// SIMATIC S7-200 SMART project (STEP 7-Micro/WIN SMART), CPU ST60

SYMBOL_TABLE Modbus TCP
//接收的MCD数据
MiddleLS         V1227.0  // 40014.0 传送带中间位置信号
EndLS            V1227.1  // 40014.1 传送带末端位置信号
GripperOpened    V1227.2  // 40014.2  夹具打开信号
GripperClosed    V1227.3  // 40014.3 夹具关闭信号
// 输出到MCD        ?0_40_0
PosAxisX         VD1200   // 40001 轴位置值
PosAxisY         VD1204   // 40003
PosAxisZ         VD1208   // 40005
PosRotat         VD1232   // 40017
SpdAxisX         VD1212   // 40007 轴速度值
SpdAxisY         VD1216   // 40009
SpdAxisZ         VD1220   // 40011
Spd3D            VD1240   // 轴组速度
SpdR             VD3500   // 旋转轴速度
SpdRotat         VD3000   // HMI 输入的旋转轴速度设置
GripperClose     V1225.0  // 40013.0 关闭夹具信号
GripperOpen      V1225.1  // 40013.1 打开夹具信号
ConvStart        V1225.2  // 40013.2 开启传送带信号
// Test Cycle    ?0_40_0
CycleNo          VW1228   // 40015 循环序号
END_SYMBOL_TABLE

SYMBOL_TABLE 系统符号
Always_On        SM0.0    // 始终接通
END_SYMBOL_TABLE

SYMBOL_TABLE movePath
///
///                       // 以下为  部分常量数值
AFTPICK          4
AFTPLACE         8
DISTANCE_PREOPERATION 10.0
ERR_AREA_RESERVED 16#8800
ERR_IN_BLOCK_OPERATION 16#8001
ERR_PARAMETRIZATION 16#8200
ERR_PROCESSING_EXTERN 16#8400
ERR_PROCESSING_INTERN 16#8600
ERR_UNDEFINED_STATE 16#8600
ERR_USER_DEFINED_CLASSE 16#9000
moveCmdActive    V1041.2  // 运动状态位
moveCmdBusy      V1041.1
moveCmdDone      V1041.0
moveCmdErr       VB1042
NO_PROCESSING    0
PICK             2
pickPosX         VD1000   // 取料轴坐标位置
pickPosY         VD1004
pickPosZ         VD1008
PLACE            6
placePosX        VD1012   // 放料轴坐标位置
placePosY        VD1016
placePosZ        VD1020
PREPICK          1
PREPLACE         5
rotatCmdDone     V1041.3  // 旋转运动完成
rotatCmdErr      VB1043   // 旋转运动报错
statBusy         V1040.1  // 运动进行中
statDone         V1040.0  // 运动完成
statError        V1040.2  // 运动报错
statGripperClose V1040.4  // 夹具关闭
statGripperOpen  V1040.3  // 夹具打开
statState        VB1050   // 运动步骤序号
statStatus       VW1052   // 运动状态信息
STATUS_EXECUTION_FINISH 16#0
STATUS_FIRST_CALL 16#7001
STATUS_NO_CALL   16#7000
STATUS_SUBSEQUENT_CALL 16#7002
TOOL_PICK        3
TOOL_PLACE       7
WAIT             9
waitPosX         VD1024   // 等待位轴坐标
waitPosY         VD1028
waitPosZ         VD1032
END_SYMBOL_TABLE

SYMBOL_TABLE HMI
EnableAxes       M1.0     // 使能轴组
HomeAxes         M1.1     // 零点设置
StopGroup        M1.2     // 停止轴组运动
ExePnP           M2.0     // 执行搬运
AbortPnP         M2.1     // 终止搬运
DonePnP          M3.0     // 搬运完成
BusyPnP          M3.1     // 搬运中
ErrPnP           M3.2     // 搬运报错
DoneMTS          M7.0     // Modbus subrutine done
XjogN            M7.1     // X轴负向手动运动
XjogP            M7.2     // X轴正向手动运动
XgoHome          M7.3     // X轴回零
YgoHome          M7.4     // Y轴回零
ZgoHome          M7.5     // Z轴回零
RgoHome          M7.6     // 旋转轴回零
EnableButton     M7.7     // 使能按钮
ErrMTS           MB6      // Modbus subrutine error
StatusPnP        MW4      // 搬运状态
END_SYMBOL_TABLE

SYMBOL_TABLE PnP
///
statPnPDone      V1100.0  // 搬运完成
statPnPBusy      V1100.1  // 正在搬运
statPnPError     V1100.2  // 搬运报错
statMovePathDone V1100.3  // 运动完成
statMovePathBusy V1100.4  // 运动中
statMovePathErr  V1100.5  // 运动报错
statCloseCmd     V1100.6  // 夹具关指令
statOpenCmd      V1100.7  // 夹具开指令
statIsClosed     V1101.0  // 夹具关状态
statIsOpened     V1101.1  // 夹具开状态
statStartPnP     V1101.2  // 搬运开始
statStartConveyor V1101.3  // 开启传送带
statPnPState     VB1108   // 搬运步骤
statPnPStatus    VW1102   // 搬运状态信息
statPnPNum       VW1104   // 搬运序号
statMovePathStatus VW1106   // movepath子程序输出状态信息
AddrPick         VB1110   // 取料坐标
PickPosX_Conf    VD1110
PickPosY_Conf    VD1114
PickPosZ_Conf    VD1118
AddrPlace        VB1130   // 放料坐标
PlacePosX_Conf   VD1130
PlacePosY_Conf   VD1134
PlacePosZ_Conf   VD1138
AddrWait         VB1150   // 等待位坐标
waitPosX_Conf    VD1150
WaitPosY_Conf    VD1154
WaitPosZ_Conf    VD1158
DISTANCE_ROWX    35       // 位置间距常量
DISTANCE_ROWY    35
END_SYMBOL_TABLE

ORGANIZATION_BLOCK MAIN:OB1
TITLE==============================================================================
// LIABILITY
// Siemens AG does not accept liability of any kind for damages arising from the use of this application, except where it is obliged to by law, in cases such as damage to items used for personal purposes, personal injury, willful damage or gross negligence.
// =============================================================================
// WARRANTY
// The program examples given are specific solutions to complex tasks which were worked on by Customer Support. We must also point out that it is not possible in the current state of the technology to exclude all errors in software programs under all conditions of use. The program examples were prepared according to the best of our knowledge. However, we cannot accept any liability beyond the standard guarantee for Class C software in accordance with our General Terms of Sale for Software Products for Automation and Drive Technology". The program examples can be purchased on the Internet as single licenses. They may not be transferred to a third party.
// =============================================================================
// 
BEGIN
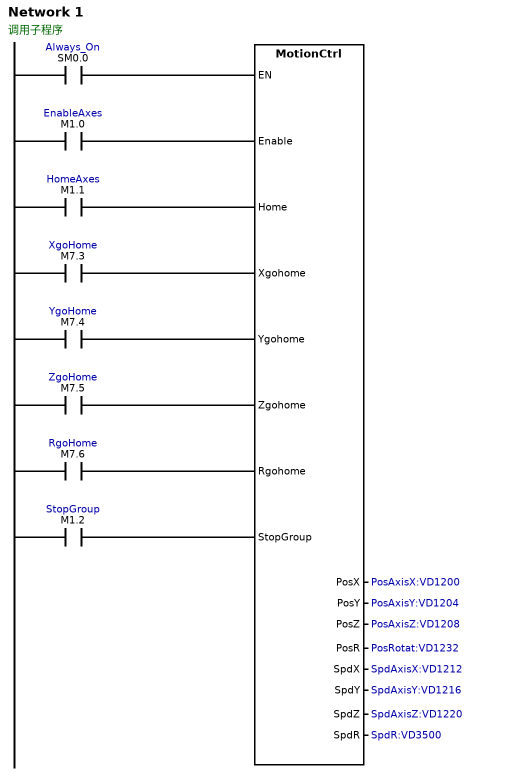
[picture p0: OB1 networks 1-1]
Network 1
// 调用子程序
LD     Always_On:SM0.0
=      L60.0
LD     EnableAxes:M1.0
=      L63.7
LD     HomeAxes:M1.1
=      L63.6
LD     XgoHome:M7.3
=      L63.5
LD     YgoHome:M7.4
=      L63.4
LD     ZgoHome:M7.5
=      L63.3
LD     RgoHome:M7.6
=      L63.2
LD     StopGroup:M1.2
=      L63.1
LD     L60.0
CALL   MotionCtrl:SBR35, L63.7, L63.6, L63.5, L63.4, L63.3, L63.2, L63.1, PosAxisX:VD1200, PosAxisY:VD1204, PosAxisZ:VD1208, PosRotat:VD1232, SpdAxisX:VD1212, SpdAxisY:VD1216, SpdAxisZ:VD1220, SpdR:VD3500
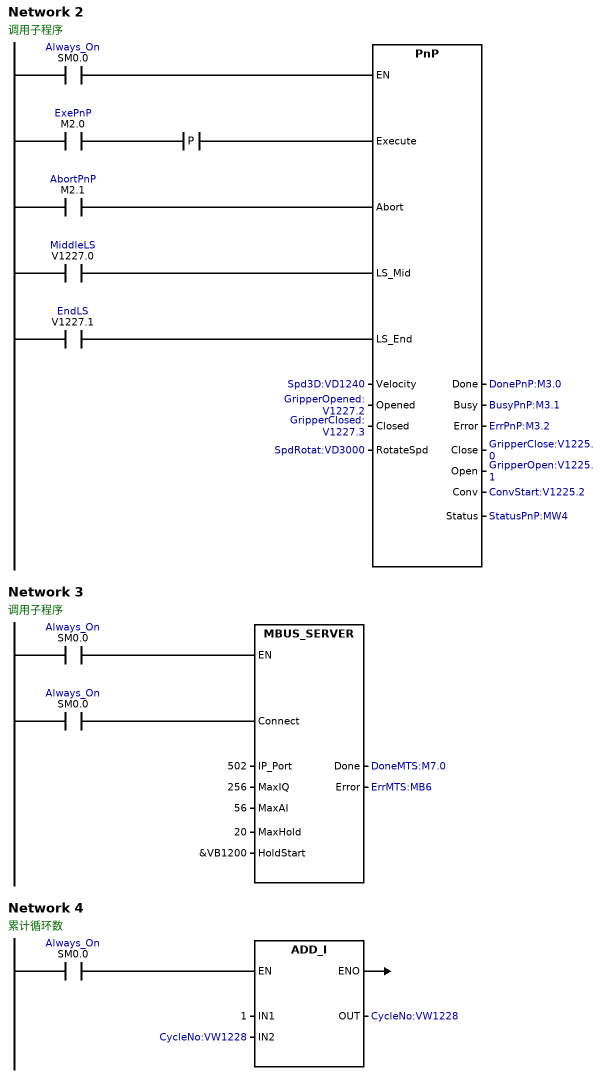
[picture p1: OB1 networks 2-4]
Network 2
// 调用子程序
LD     Always_On:SM0.0
=      L60.0
LD     ExePnP:M2.0
EU
=      L63.7
LD     AbortPnP:M2.1
=      L63.6
LD     MiddleLS:V1227.0
=      L63.5
LD     EndLS:V1227.1
=      L63.4
LD     L60.0
CALL   PnP:SBR36, L63.7, L63.6, L63.5, L63.4, Spd3D:VD1240, GripperOpened:V1227.2, GripperClosed:V1227.3, SpdRotat:VD3000, DonePnP:M3.0, BusyPnP:M3.1, ErrPnP:M3.2, GripperClose:V1225.0, GripperOpen:V1225.1, ConvStart:V1225.2, StatusPnP:MW4
Network 3
// 调用子程序
LD     Always_On:SM0.0
=      L60.0
LD     Always_On:SM0.0
=      L63.7
LD     L60.0
CALL   MBUS_SERVER:SBR39, L63.7, 502, 256, 56, 20, &VB1200, DoneMTS:M7.0, ErrMTS:MB6
Network 4
// 累计循环数
LD     Always_On:SM0.0
+I     1, CycleNo:VW1228
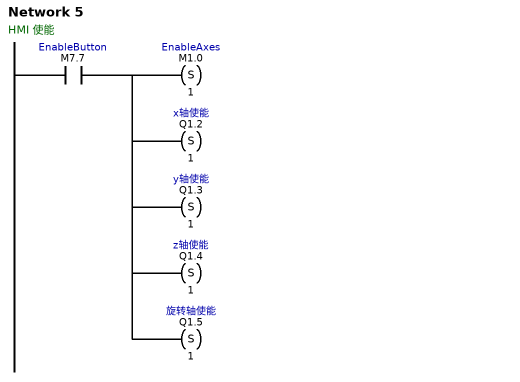
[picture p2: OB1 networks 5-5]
Network 5
// HMI 使能
LD     EnableButton:M7.7
S      EnableAxes:M1.0, 1
S      x轴使能:Q1.2, 1
S      y轴使能:Q1.3, 1
S      z轴使能:Q1.4, 1
S      旋转轴使能:Q1.5, 1
END_ORGANIZATION_BLOCK

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
SUBROUTINE_BLOCK MotionCtrl:SBR35
TITLE=对运动轴和轴组的初始化
VAR_INPUT
Enable:BOOL;	// L0.0 使能输入
Home:BOOL;	// L0.1 设零点
Xgohome:BOOL;	// L0.2 X轴回零点
Ygohome:BOOL;	// L0.3 Y轴回零点
Zgohome:BOOL;	// L0.4 Z轴回零点
Rgohome:BOOL;	// L0.5 旋转轴回零点
StopGroup:BOOL;	// L0.6 停止轴组运动
END_VAR
VAR_OUTPUT
PosX:REAL;	// LD1 X轴位置
PosY:REAL;	// LD5 Y轴位置
PosZ:REAL;	// LD9 Z轴位置
PosR:REAL;	// LD13 旋转轴位置
SpdX:REAL;	// LD17 X轴速度
SpdY:REAL;	// LD21 Y轴速度
SpdZ:REAL;	// LD25 Z轴速度
SpdR:REAL;	// LD29 旋转轴速度
END_VAR
VAR
tempDone0:BOOL;	// L33.0 
tempDone1:BOOL;	// L33.1 
tempDone2:BOOL;	// L33.2 
tempDone3:BOOL;	// L33.3 
tempErr0:BYTE;	// LB34 
tempErr1:BYTE;	// LB35 
tempErr2:BYTE;	// LB36 
tempErr3:BYTE;	// LB37 
tempPos:REAL;	// LD38 
tempSpd:REAL;	// LD42 
tempDir:BOOL;	// L46.0 
tempHome0:BOOL;	// L46.1 
tempHome1:BOOL;	// L46.2 
tempHome2:BOOL;	// L46.3 
tempHome3:BOOL;	// L46.4 
tempStopDone:BOOL;	// L46.5 
tempStopBusy:BOOL;	// L46.6 
tempStopActive:BOOL;	// L46.7 
tempStopErr:BYTE;	// LB47 
tempXhomeDone:BOOL;	// L48.0 
tempXhomeErr:BYTE;	// LB49 
tempYhomeDone:BOOL;	// L50.0 
tempYhomeErr:BYTE;	// LB51 
tempZhomeDone:BOOL;	// L52.0 
tempZhomeErr:BYTE;	// LB53 
tempRhomeErr:BYTE;	// LB54 
tempRun:BOOL;	// L55.0 
dir:BOOL;	// L55.1 
tempRhomeDone:BOOL;	// L55.2 
END_VAR
BEGIN
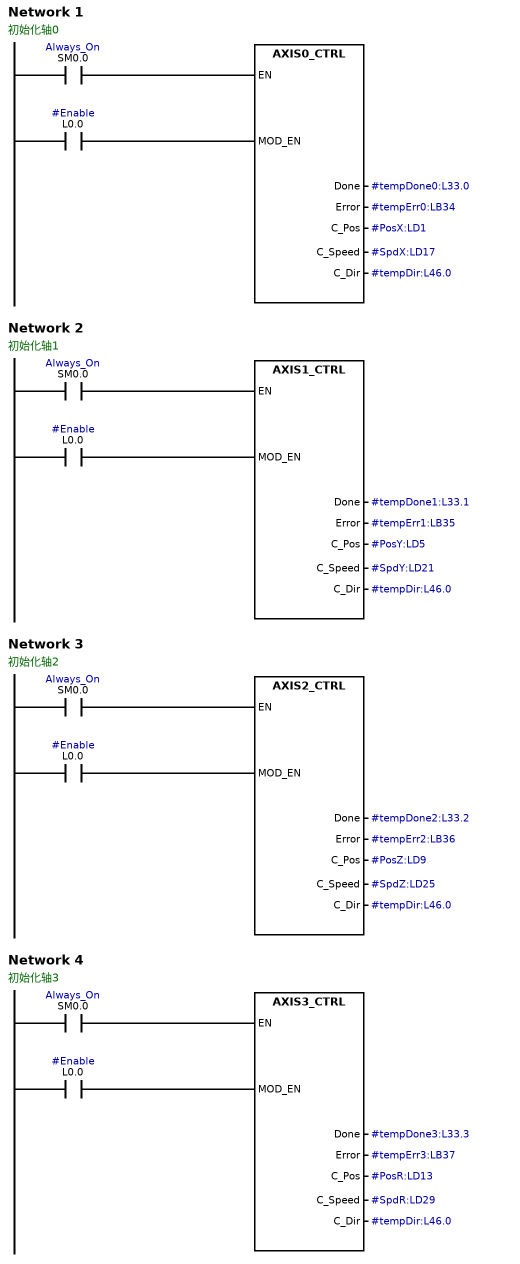
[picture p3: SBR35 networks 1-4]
Network 1
// 初始化轴0
LD     Always_On:SM0.0
=      L60.0
LD     #Enable:L0.0
=      L63.7
LD     L60.0
CALL   AXIS0_CTRL:SBR0, L63.7, #tempDone0:L33.0, #tempErr0:LB34, #PosX:LD1, #SpdX:LD17, #tempDir:L46.0
Network 2
// 初始化轴1
LD     Always_On:SM0.0
=      L60.0
LD     #Enable:L0.0
=      L63.7
LD     L60.0
CALL   AXIS1_CTRL:SBR11, L63.7, #tempDone1:L33.1, #tempErr1:LB35, #PosY:LD5, #SpdY:LD21, #tempDir:L46.0
Network 3
// 初始化轴2
LD     Always_On:SM0.0
=      L60.0
LD     #Enable:L0.0
=      L63.7
LD     L60.0
CALL   AXIS2_CTRL:SBR22, L63.7, #tempDone2:L33.2, #tempErr2:LB36, #PosZ:LD9, #SpdZ:LD25, #tempDir:L46.0
Network 4
// 初始化轴3
LD     Always_On:SM0.0
=      L60.0
LD     #Enable:L0.0
=      L63.7
LD     L60.0
CALL   AXIS3_CTRL:SBR33, L63.7, #tempDone3:L33.3, #tempErr3:LB37, #PosR:LD13, #SpdR:LD29, #tempDir:L46.0
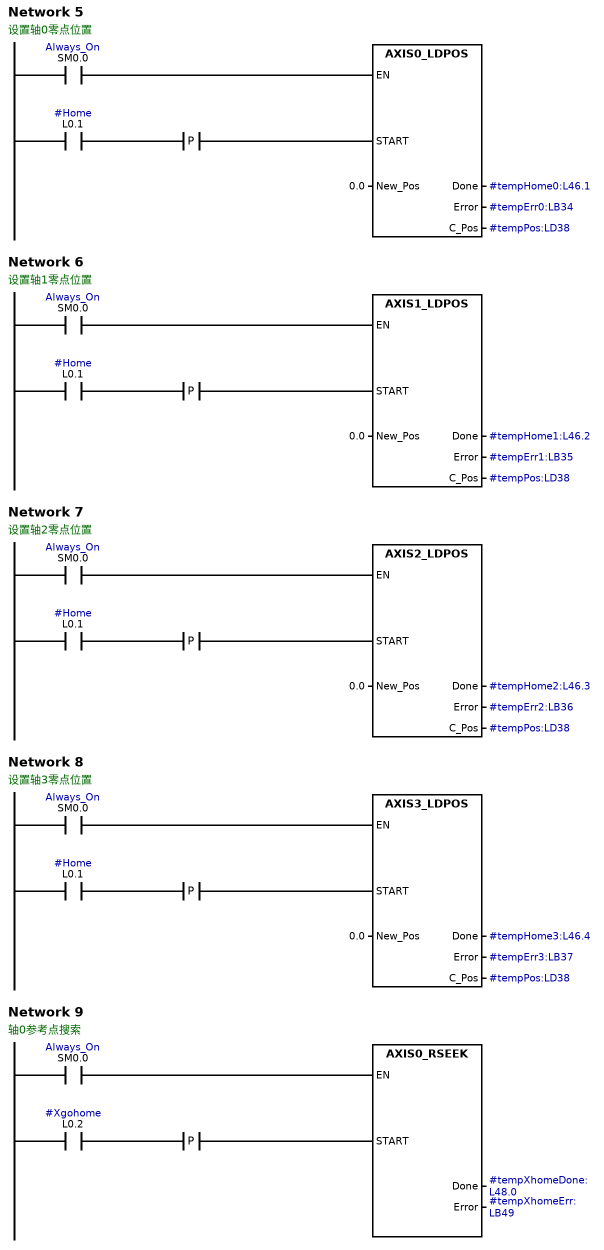
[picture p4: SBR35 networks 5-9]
Network 5
// 设置轴0零点位置
LD     Always_On:SM0.0
=      L60.0
LD     #Home:L0.1
EU
=      L63.7
LD     L60.0
CALL   AXIS0_LDPOS:SBR6, L63.7, 0.0, #tempHome0:L46.1, #tempErr0:LB34, #tempPos:LD38
Network 6
// 设置轴1零点位置
LD     Always_On:SM0.0
=      L60.0
LD     #Home:L0.1
EU
=      L63.7
LD     L60.0
CALL   AXIS1_LDPOS:SBR17, L63.7, 0.0, #tempHome1:L46.2, #tempErr1:LB35, #tempPos:LD38
Network 7
// 设置轴2零点位置
LD     Always_On:SM0.0
=      L60.0
LD     #Home:L0.1
EU
=      L63.7
LD     L60.0
CALL   AXIS2_LDPOS:SBR28, L63.7, 0.0, #tempHome2:L46.3, #tempErr2:LB36, #tempPos:LD38
Network 8
// 设置轴3零点位置
LD     Always_On:SM0.0
=      L60.0
LD     #Home:L0.1
EU
=      L63.7
LD     L60.0
CALL   AXIS3_LDPOS:SBR44, L63.7, 0.0, #tempHome3:L46.4, #tempErr3:LB37, #tempPos:LD38
Network 9
// 轴0参考点搜索
LD     Always_On:SM0.0
=      L60.0
LD     #Xgohome:L0.2
EU
=      L63.7
LD     L60.0
CALL   AXIS0_RSEEK:SBR4, L63.7, #tempXhomeDone:L48.0, #tempXhomeErr:LB49
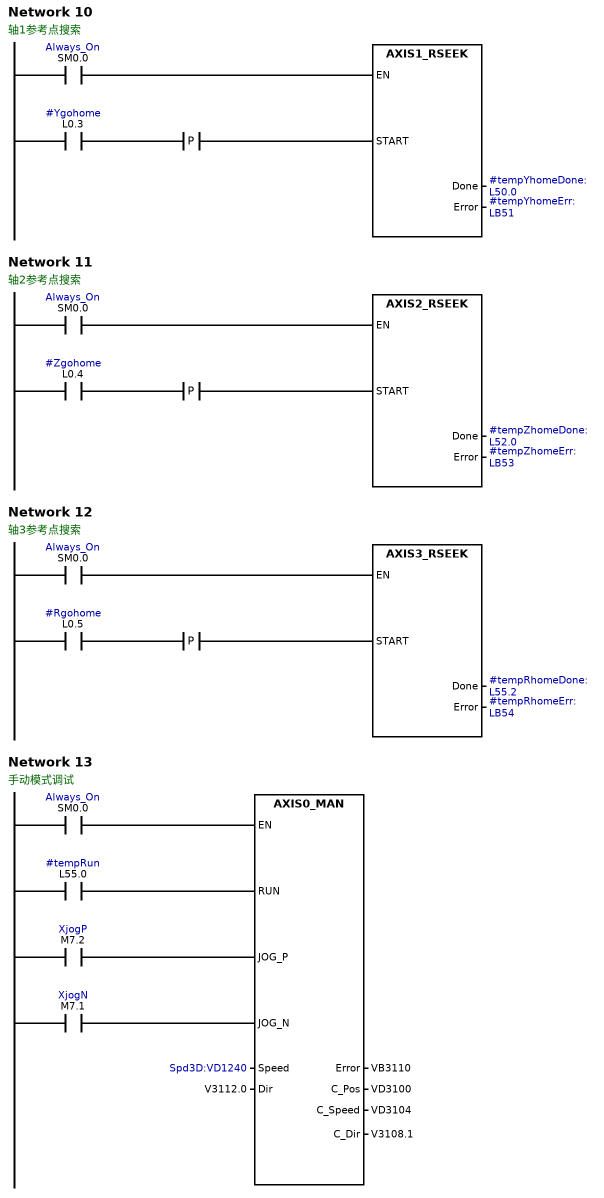
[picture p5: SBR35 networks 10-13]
Network 10
// 轴1参考点搜索
LD     Always_On:SM0.0
=      L60.0
LD     #Ygohome:L0.3
EU
=      L63.7
LD     L60.0
CALL   AXIS1_RSEEK:SBR15, L63.7, #tempYhomeDone:L50.0, #tempYhomeErr:LB51
Network 11
// 轴2参考点搜索
LD     Always_On:SM0.0
=      L60.0
LD     #Zgohome:L0.4
EU
=      L63.7
LD     L60.0
CALL   AXIS2_RSEEK:SBR26, L63.7, #tempZhomeDone:L52.0, #tempZhomeErr:LB53
Network 12
// 轴3参考点搜索
LD     Always_On:SM0.0
=      L60.0
LD     #Rgohome:L0.5
EU
=      L63.7
LD     L60.0
CALL   AXIS3_RSEEK:SBR42, L63.7, #tempRhomeDone:L55.2, #tempRhomeErr:LB54
Network 13
// 手动模式调试
LD     Always_On:SM0.0
=      L60.0
LD     #tempRun:L55.0
=      L63.7
LD     XjogP:M7.2
=      L63.6
LD     XjogN:M7.1
=      L63.5
LD     L60.0
CALL   AXIS0_MAN:SBR1, L63.7, L63.6, L63.5, Spd3D:VD1240, V3112.0, VB3110, VD3100, VD3104, V3108.1
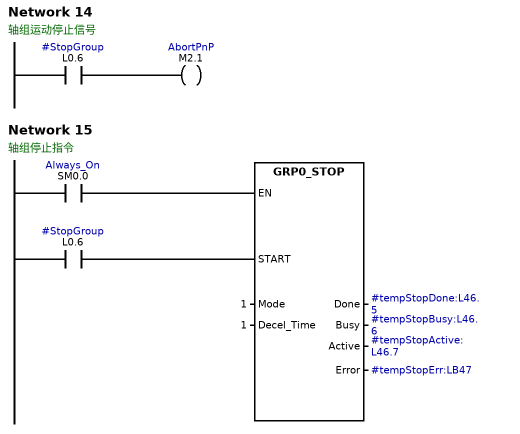
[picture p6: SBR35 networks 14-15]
Network 14
// 轴组运动停止信号
LD     #StopGroup:L0.6
=      AbortPnP:M2.1
Network 15
// 轴组停止指令
LD     Always_On:SM0.0
=      L60.0
LD     #StopGroup:L0.6
=      L63.7
LD     L60.0
CALL   GRP0_STOP:SBR51, L63.7, 1, 1, #tempStopDone:L46.5, #tempStopBusy:L46.6, #tempStopActive:L46.7, #tempStopErr:LB47
END_SUBROUTINE_BLOCK

SUBROUTINE_BLOCK PnP:SBR36
TITLE=搬运流程逻辑
VAR_INPUT
Execute:BOOL;	// L0.0 执行，上升沿触发
Abort:BOOL;	// L0.1 终止搬运
LS_Mid:BOOL;	// L0.2 传送带中间位
LS_End:BOOL;	// L0.3 传送带尾端位
Velocity:REAL;	// LD1 速度值
Opened:BOOL;	// L5.0 打开夹具
Closed:BOOL;	// L5.1 关闭夹具
RotateSpd:REAL;	// LD6 旋转轴速度
END_VAR
VAR_OUTPUT
Done:BOOL;	// L10.0 完成状态位
Busy:BOOL;	// L10.1 忙碌状态位
Error:BOOL;	// L10.2 错误位
Close:BOOL;	// L10.3 夹具关闭
Open:BOOL;	// L10.4 夹具打开
Conv:BOOL;	// L10.5 传送带指令
Status:WORD;	// LW11 状态信息输出
END_VAR
VAR
tempRowX:INT;	// LW13 
tempRowY:INT;	// LW15 
tempPosAddInt:INT;	// LW17 
tempPosAddDint:DINT;	// LD19 
END_VAR
BEGIN
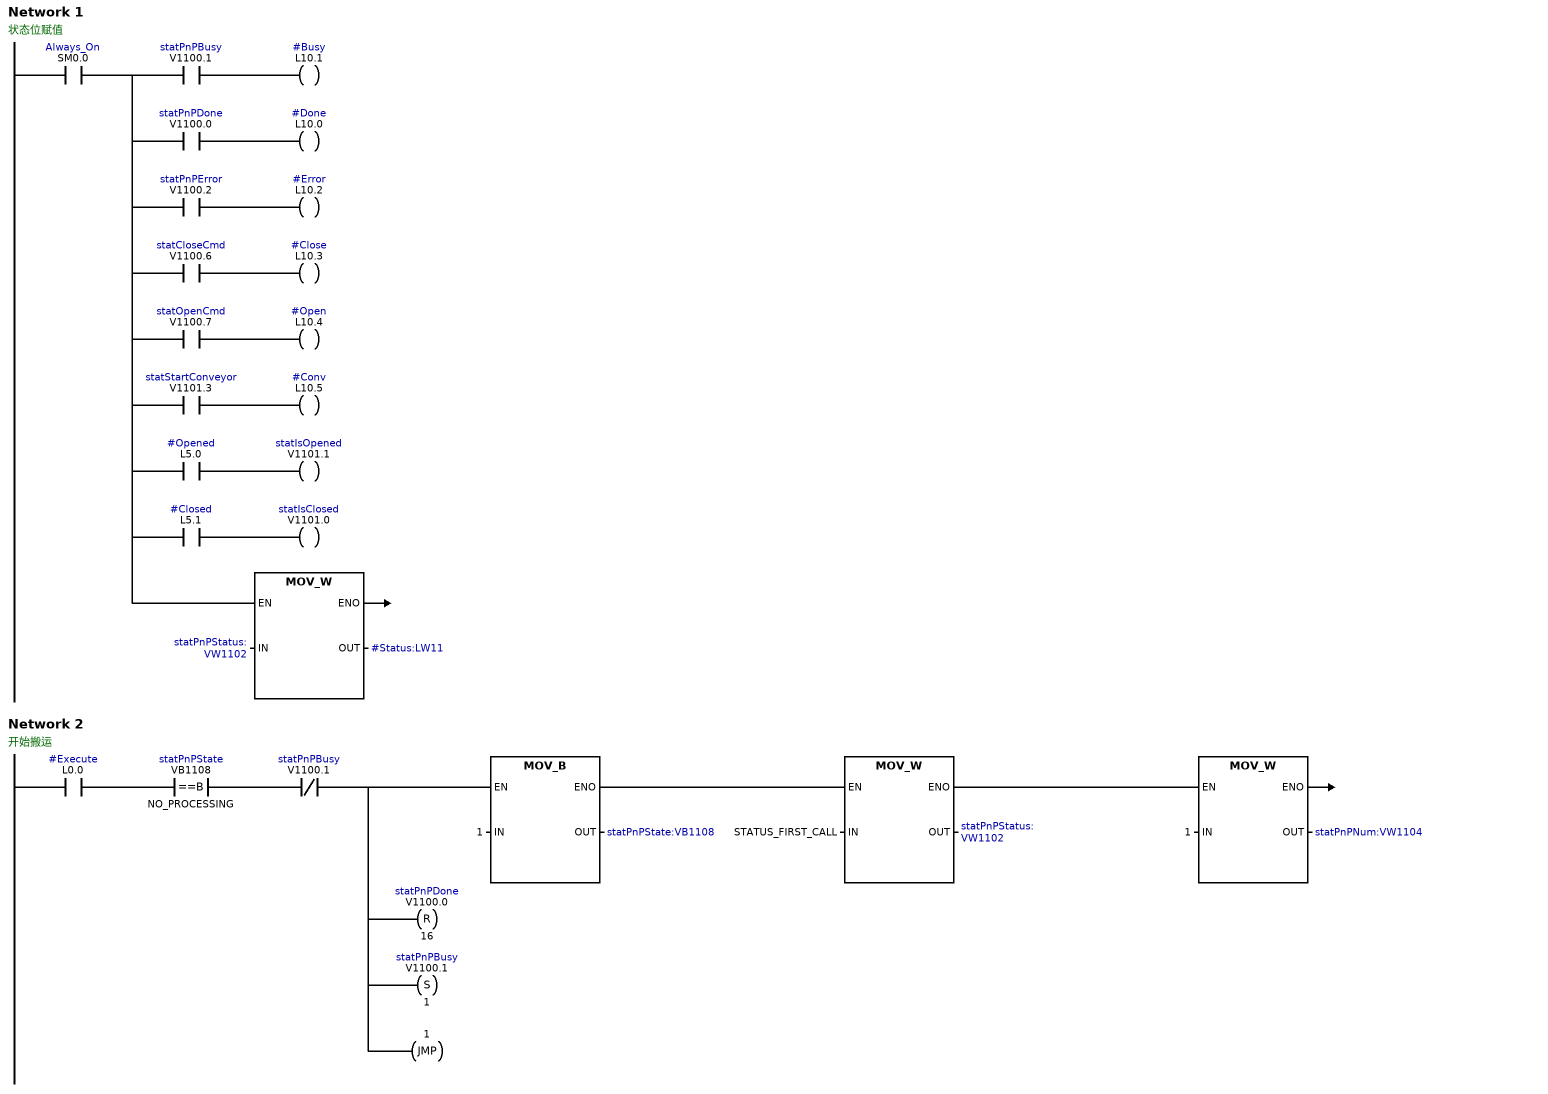
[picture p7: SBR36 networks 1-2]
Network 1
// 状态位赋值
LD     Always_On:SM0.0
LPS
A      statPnPBusy:V1100.1
=      #Busy:L10.1
LRD
A      statPnPDone:V1100.0
=      #Done:L10.0
LRD
A      statPnPError:V1100.2
=      #Error:L10.2
LRD
A      statCloseCmd:V1100.6
=      #Close:L10.3
LRD
A      statOpenCmd:V1100.7
=      #Open:L10.4
LRD
A      statStartConveyor:V1101.3
=      #Conv:L10.5
LRD
A      #Opened:L5.0
=      statIsOpened:V1101.1
LRD
A      #Closed:L5.1
=      statIsClosed:V1101.0
LPP
MOVW   statPnPStatus:VW1102, #Status:LW11
Network 2
// 开始搬运
LD     #Execute:L0.0
AB=    statPnPState:VB1108, NO_PROCESSING
AN     statPnPBusy:V1100.1
LPS
MOVB   1, statPnPState:VB1108
AENO
MOVW   STATUS_FIRST_CALL, statPnPStatus:VW1102
AENO
MOVW   1, statPnPNum:VW1104
LRD
R      statPnPDone:V1100.0, 16
LRD
S      statPnPBusy:V1100.1, 1
LPP
JMP    1
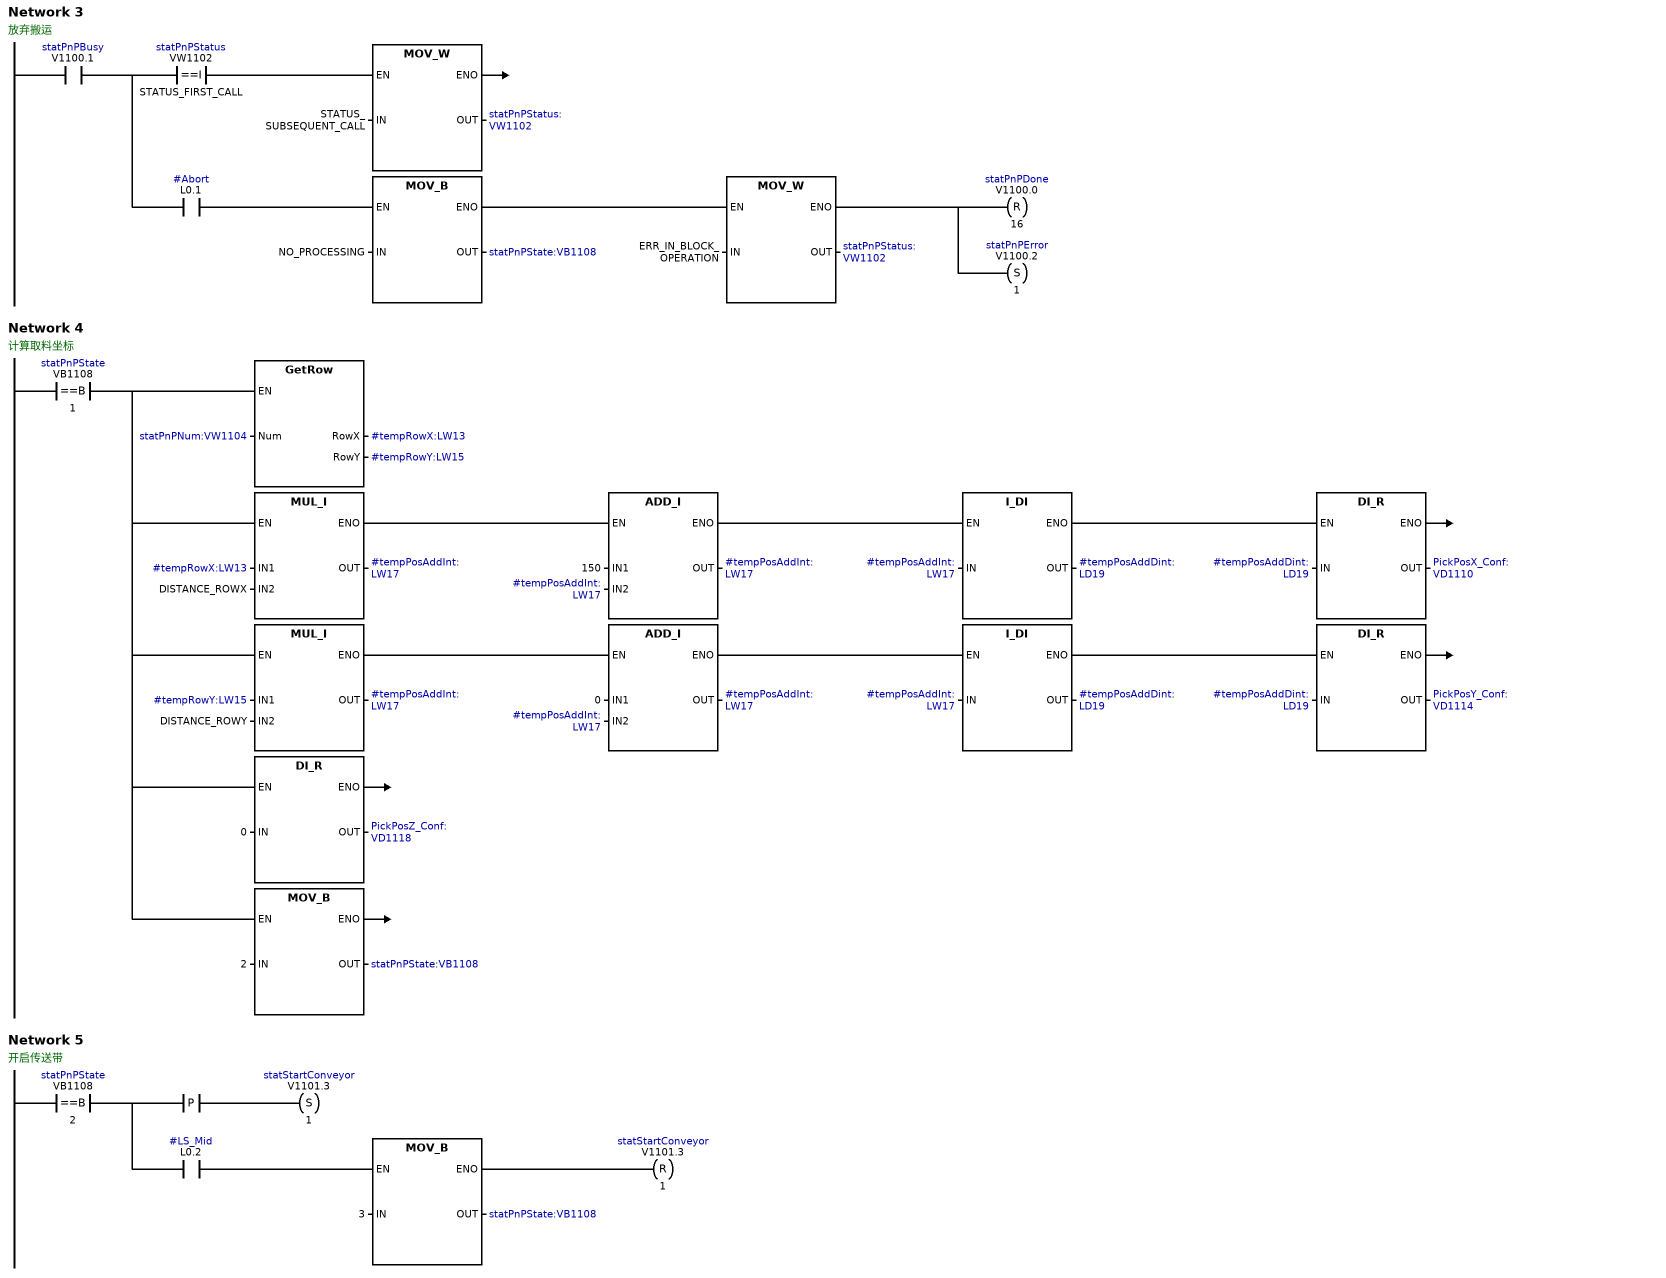
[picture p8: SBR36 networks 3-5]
Network 3
// 放弃搬运
LD     statPnPBusy:V1100.1
LPS
AW=    statPnPStatus:VW1102, STATUS_FIRST_CALL
MOVW   STATUS_SUBSEQUENT_CALL, statPnPStatus:VW1102
LPP
A      #Abort:L0.1
MOVB   NO_PROCESSING, statPnPState:VB1108
AENO
MOVW   ERR_IN_BLOCK_OPERATION, statPnPStatus:VW1102
AENO
R      statPnPDone:V1100.0, 16
S      statPnPError:V1100.2, 1
Network 4
// 计算取料坐标
LDB=   statPnPState:VB1108, 1
LPS
CALL   GetRow:SBR38, statPnPNum:VW1104, #tempRowX:LW13, #tempRowY:LW15
MOVW   #tempRowX:LW13, #tempPosAddInt:LW17
AENO
*I     DISTANCE_ROWX, #tempPosAddInt:LW17
AENO
+I     150, #tempPosAddInt:LW17
AENO
ITD    #tempPosAddInt:LW17, #tempPosAddDint:LD19
AENO
DTR    #tempPosAddDint:LD19, PickPosX_Conf:VD1110
LRD
MOVW   #tempRowY:LW15, #tempPosAddInt:LW17
AENO
*I     DISTANCE_ROWY, #tempPosAddInt:LW17
AENO
+I     0, #tempPosAddInt:LW17
AENO
ITD    #tempPosAddInt:LW17, #tempPosAddDint:LD19
AENO
DTR    #tempPosAddDint:LD19, PickPosY_Conf:VD1114
LRD
DTR    0, PickPosZ_Conf:VD1118
LPP
MOVB   2, statPnPState:VB1108
Network 5
// 开启传送带
LDB=   statPnPState:VB1108, 2
LPS
EU
S      statStartConveyor:V1101.3, 1
LPP
A      #LS_Mid:L0.2
MOVB   3, statPnPState:VB1108
AENO
R      statStartConveyor:V1101.3, 1
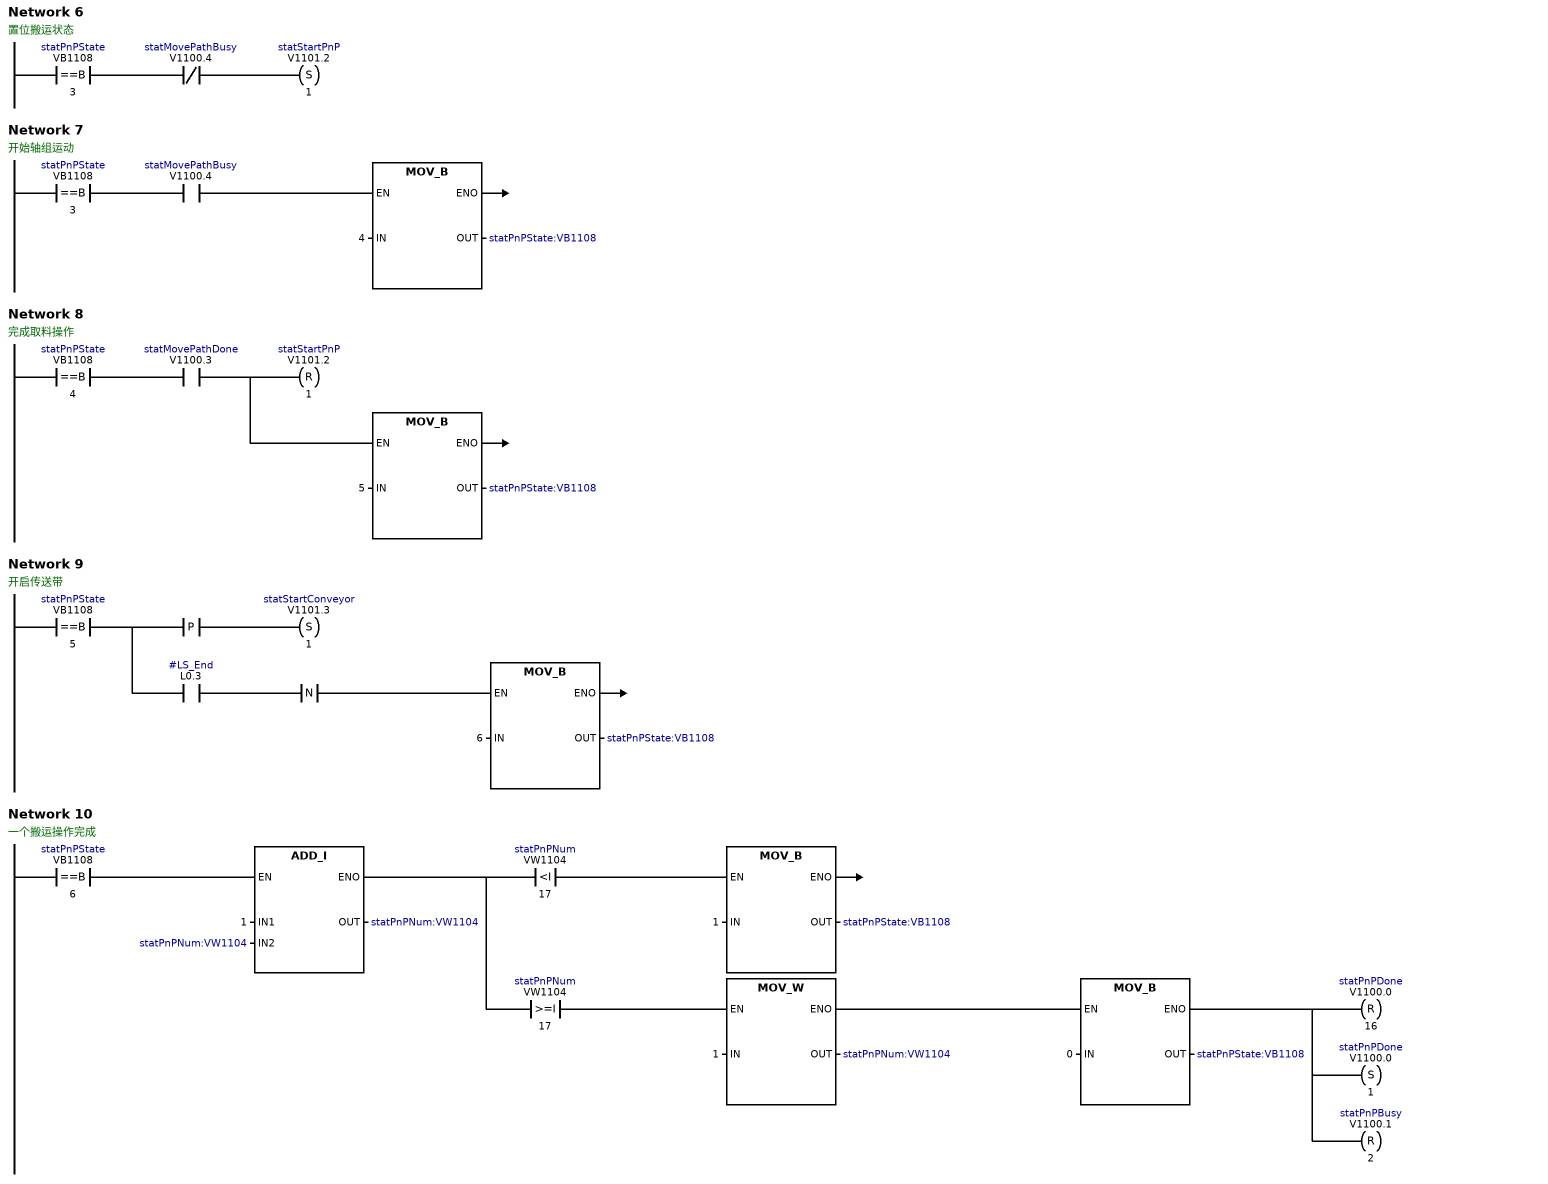
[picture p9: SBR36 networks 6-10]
Network 6
// 置位搬运状态
LDB=   statPnPState:VB1108, 3
AN     statMovePathBusy:V1100.4
S      statStartPnP:V1101.2, 1
Network 7
// 开始轴组运动
LDB=   statPnPState:VB1108, 3
A      statMovePathBusy:V1100.4
MOVB   4, statPnPState:VB1108
Network 8
// 完成取料操作
LDB=   statPnPState:VB1108, 4
A      statMovePathDone:V1100.3
R      statStartPnP:V1101.2, 1
MOVB   5, statPnPState:VB1108
Network 9
// 开启传送带
LDB=   statPnPState:VB1108, 5
LPS
EU
S      statStartConveyor:V1101.3, 1
LPP
A      #LS_End:L0.3
ED
MOVB   6, statPnPState:VB1108
Network 10
// 一个搬运操作完成
LDB=   statPnPState:VB1108, 6
+I     1, statPnPNum:VW1104
AENO
LPS
AW<    statPnPNum:VW1104, 17
MOVB   1, statPnPState:VB1108
LPP
AW>=   statPnPNum:VW1104, 17
MOVW   1, statPnPNum:VW1104
AENO
MOVB   0, statPnPState:VB1108
AENO
R      statPnPDone:V1100.0, 16
S      statPnPDone:V1100.0, 1
R      statPnPBusy:V1100.1, 2
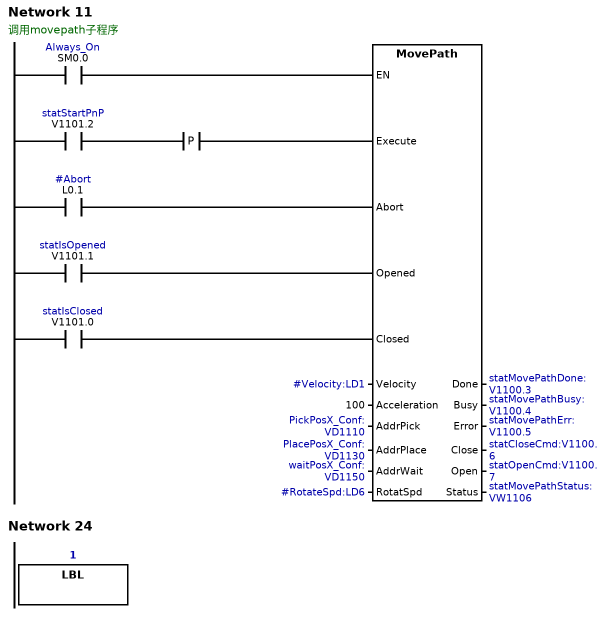
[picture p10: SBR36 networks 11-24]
Network 11
// 调用movepath子程序
LD     Always_On:SM0.0
=      L60.0
LD     statStartPnP:V1101.2
EU
=      L63.7
LD     #Abort:L0.1
=      L63.6
LD     statIsOpened:V1101.1
=      L63.5
LD     statIsClosed:V1101.0
=      L63.4
LD     L60.0
CALL   MovePath:SBR127, L63.7, L63.6, L63.5, L63.4, #Velocity:LD1, 100, PickPosX_Conf:VD1110, PlacePosX_Conf:VD1130, waitPosX_Conf:VD1150, #RotateSpd:LD6, statMovePathDone:V1100.3, statMovePathBusy:V1100.4, statMovePathErr:V1100.5, statCloseCmd:V1100.6, statOpenCmd:V1100.7, statMovePathStatus:VW1106
Network 24
LBL    1
END_SUBROUTINE_BLOCK

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
SUBROUTINE_BLOCK GetRow:SBR38
TITLE=计算取物料位置坐标
VAR_INPUT
Num:INT;	// LW0 物料序号
END_VAR
VAR_OUTPUT
RowX:INT;	// LW2 X轴行数
RowY:INT;	// LW4 Y轴行数
END_VAR
VAR
tempDWR:BOOL;	// L6.0 
tempMod:INT;	// LW7 
tempDiv:INT;	// LW9 
END_VAR
BEGIN
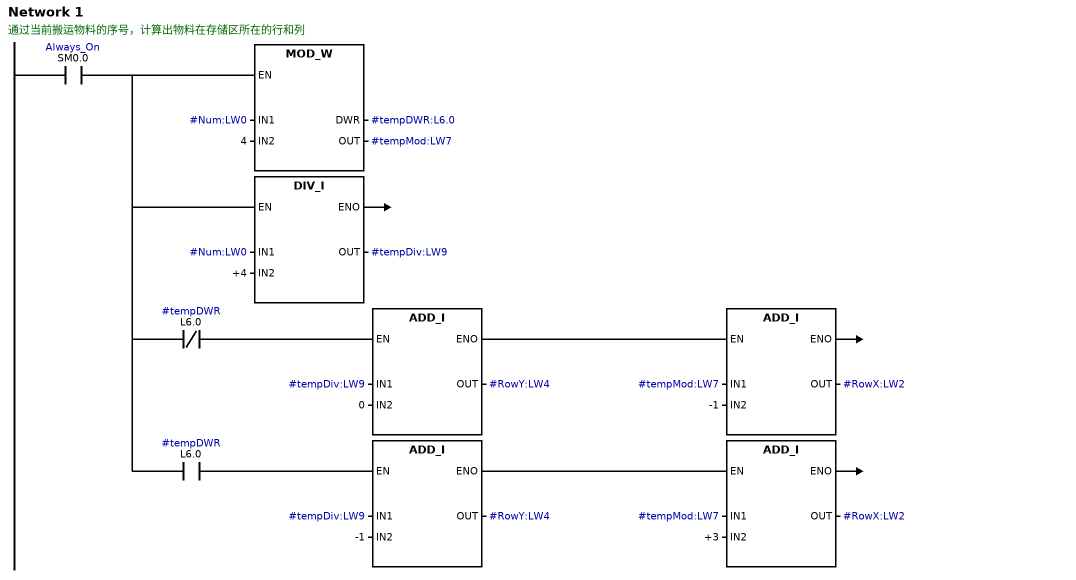
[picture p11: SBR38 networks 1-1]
Network 1
// 通过当前搬运物料的序号，计算出物料在存储区所在的行和列
LD     Always_On:SM0.0
LPS
CALL   MOD_W:SBR37, #Num:LW0, 4, #tempDWR:L6.0, #tempMod:LW7
MOVW   #Num:LW0, #tempDiv:LW9
/I     +4, #tempDiv:LW9
AN     #tempDWR:L6.0
MOVW   #tempDiv:LW9, #RowY:LW4
AENO
+I     0, #RowY:LW4
AENO
MOVW   #tempMod:LW7, #RowX:LW2
+I     -1, #RowX:LW2
LPP
A      #tempDWR:L6.0
MOVW   #tempDiv:LW9, #RowY:LW4
AENO
+I     -1, #RowY:LW4
AENO
MOVW   #tempMod:LW7, #RowX:LW2
+I     +3, #RowX:LW2
END_SUBROUTINE_BLOCK

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
SUBROUTINE_BLOCK MovePath:SBR127
TITLE=运动步骤控制
VAR_INPUT
Execute:BOOL;	// L0.0 执行，上升沿触发
Abort:BOOL;	// L0.1 终止运动
Opened:BOOL;	// L0.2 夹具已打开
Closed:BOOL;	// L0.3 夹具已打开
Velocity:REAL;	// LD1 速度值
Acceleration:DINT;	// LD5 加速度值
AddrPick:DWORD;	// LD9 取料位置
AddrPlace:DWORD;	// LD13 放料位置
AddrWait:DWORD;	// LD17 等待位置
RotatSpd:REAL;	// LD21 旋转轴速度
END_VAR
VAR_OUTPUT
Done:BOOL;	// L25.0 完成输出位
Busy:BOOL;	// L25.1 忙碌输出位
Error:BOOL;	// L25.2 错误输出位
Close:BOOL;	// L25.3 夹具关闭
Open:BOOL;	// L25.4 夹具打开
Status:WORD;	// LW26 状态输出位
END_VAR
VAR
tempPosX:REAL;	// LD28 
tempPosY:REAL;	// LD32 
tempPosZ:REAL;	// LD36 
tempRotatPos:REAL;	// LD40 
tempRotateSpd:REAL;	// LD44 
END_VAR
BEGIN
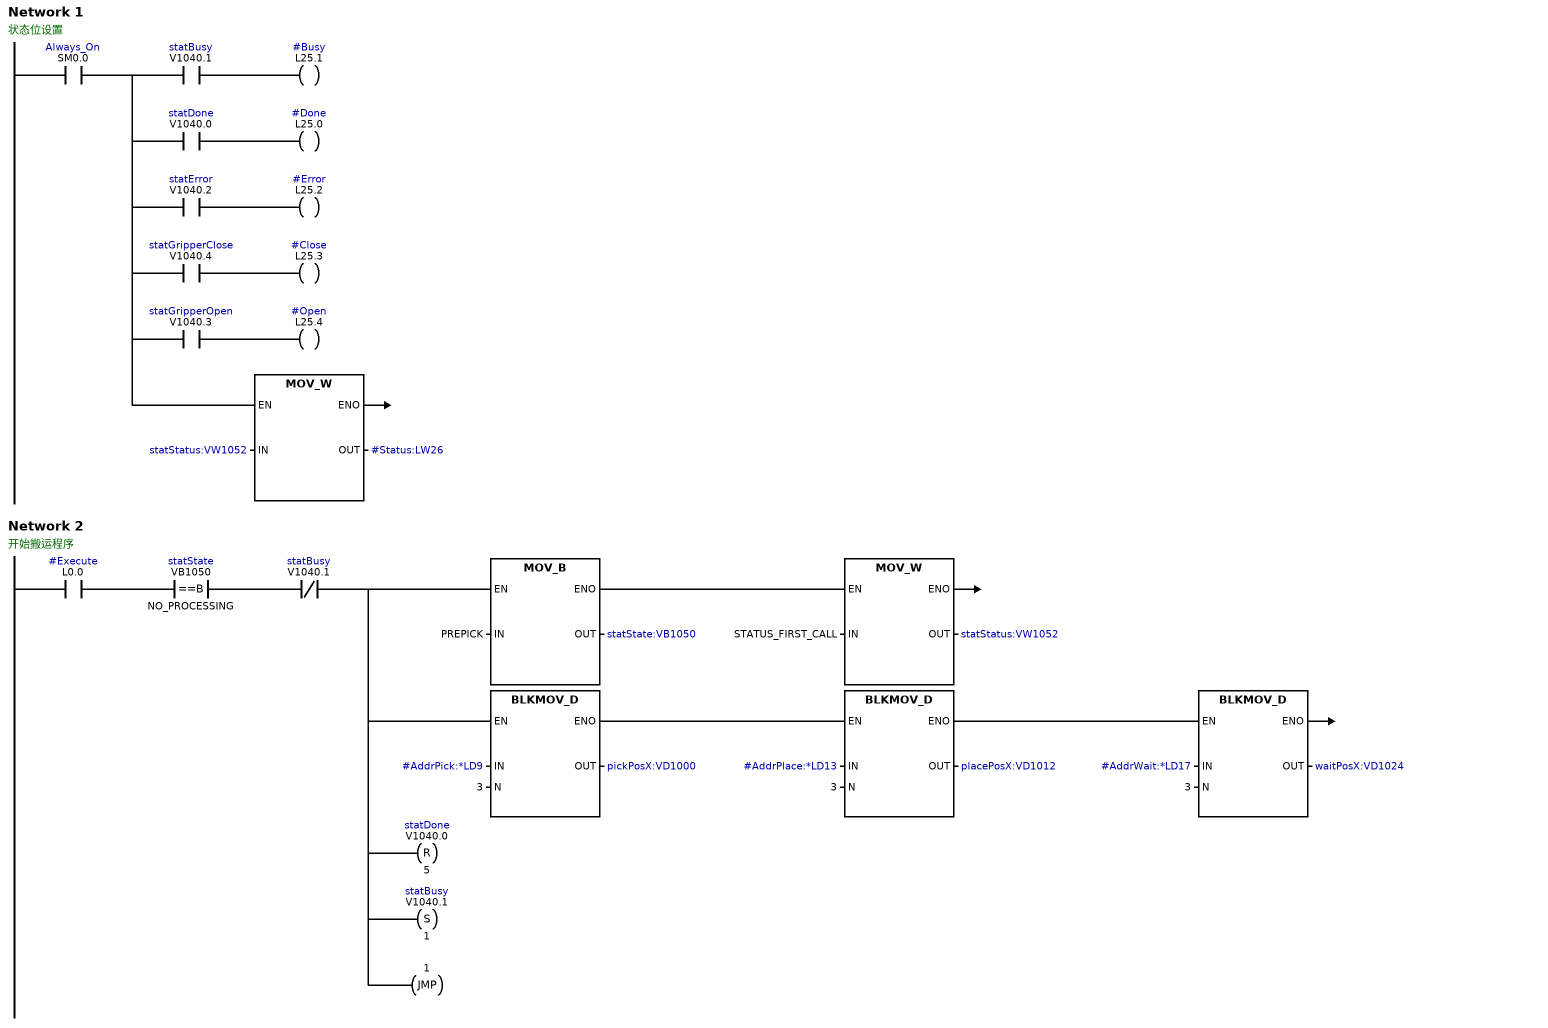
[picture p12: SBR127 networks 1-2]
Network 1
// 状态位设置
LD     Always_On:SM0.0
LPS
A      statBusy:V1040.1
=      #Busy:L25.1
LRD
A      statDone:V1040.0
=      #Done:L25.0
LRD
A      statError:V1040.2
=      #Error:L25.2
LRD
A      statGripperClose:V1040.4
=      #Close:L25.3
LRD
A      statGripperOpen:V1040.3
=      #Open:L25.4
LPP
MOVW   statStatus:VW1052, #Status:LW26
Network 2
// 开始搬运程序
LD     #Execute:L0.0
AB=    statState:VB1050, NO_PROCESSING
AN     statBusy:V1040.1
LPS
MOVB   PREPICK, statState:VB1050
AENO
MOVW   STATUS_FIRST_CALL, statStatus:VW1052
LRD
BMD    *#AddrPick:LD9, pickPosX:VD1000, 3
AENO
BMD    *#AddrPlace:LD13, placePosX:VD1012, 3
AENO
BMD    *#AddrWait:LD17, waitPosX:VD1024, 3
LRD
R      statDone:V1040.0, 5
LRD
S      statBusy:V1040.1, 1
LPP
JMP    1
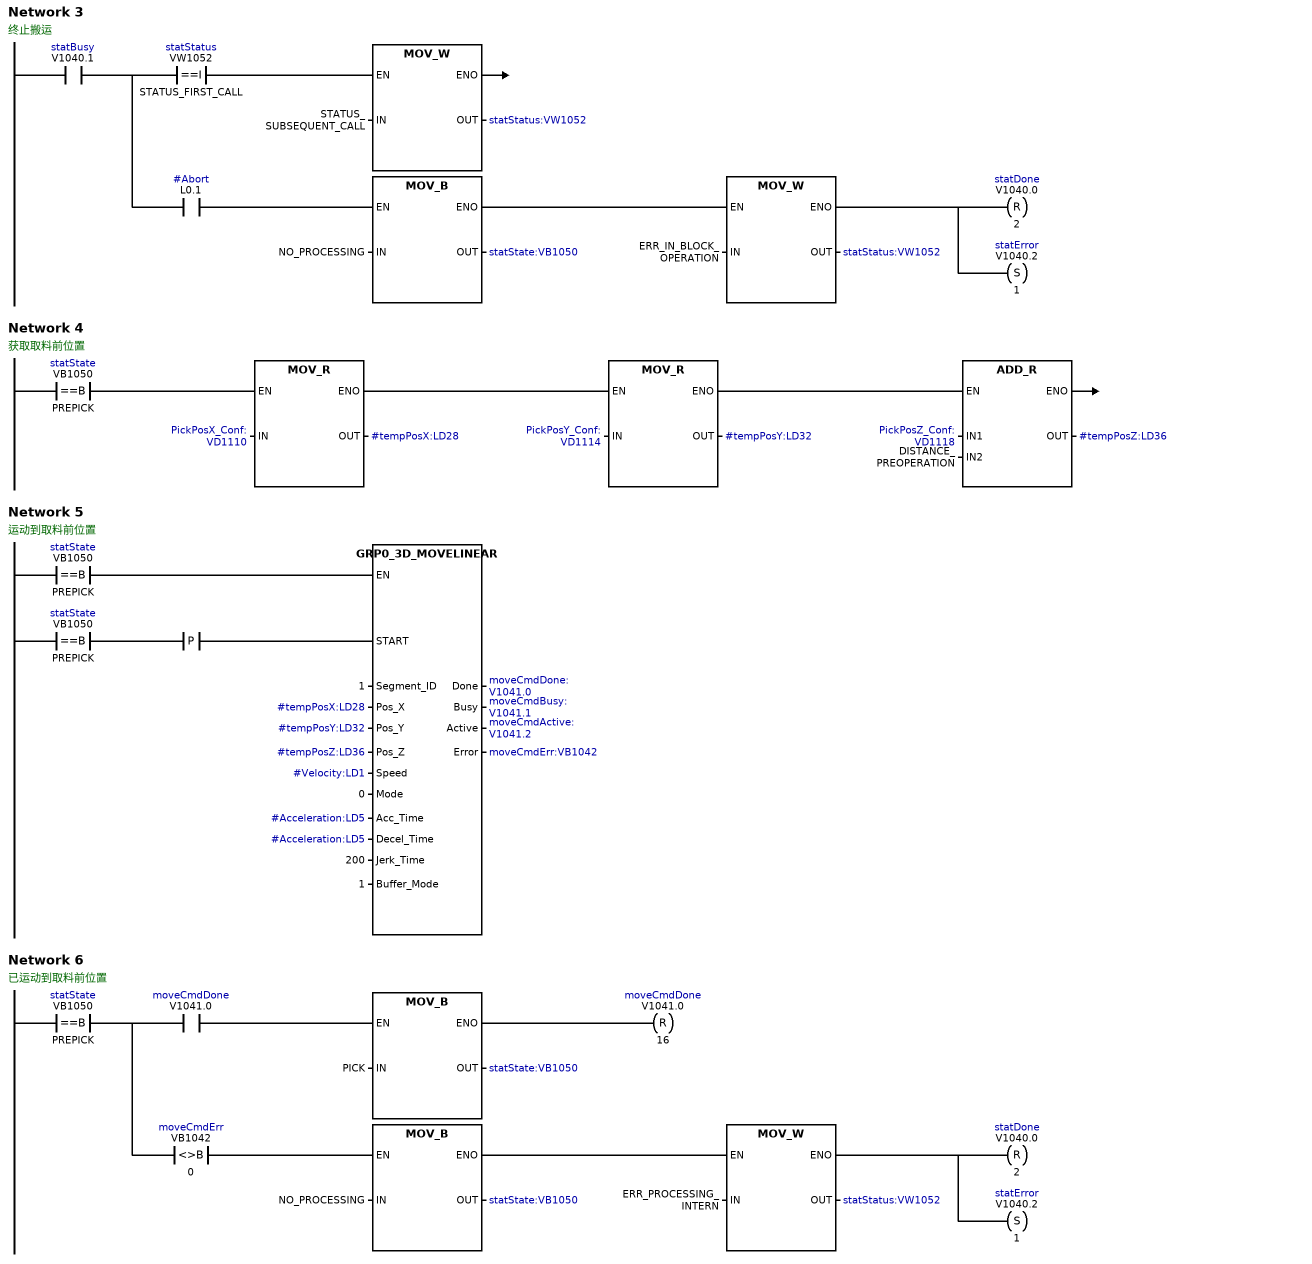
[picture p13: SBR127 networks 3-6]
Network 3
// 终止搬运
LD     statBusy:V1040.1
LPS
AW=    statStatus:VW1052, STATUS_FIRST_CALL
MOVW   STATUS_SUBSEQUENT_CALL, statStatus:VW1052
LPP
A      #Abort:L0.1
MOVB   NO_PROCESSING, statState:VB1050
AENO
MOVW   ERR_IN_BLOCK_OPERATION, statStatus:VW1052
AENO
R      statDone:V1040.0, 2
S      statError:V1040.2, 1
Network 4
// 获取取料前位置
LDB=   statState:VB1050, PREPICK
MOVR   PickPosX_Conf:VD1110, #tempPosX:LD28
AENO
MOVR   PickPosY_Conf:VD1114, #tempPosY:LD32
AENO
MOVR   PickPosZ_Conf:VD1118, #tempPosZ:LD36
+R     DISTANCE_PREOPERATION, #tempPosZ:LD36
Network 5
// 运动到取料前位置
LDB=   statState:VB1050, PREPICK
=      L60.0
LDB=   statState:VB1050, PREPICK
EU
=      L63.7
LD     L60.0
CALL   GRP0_3D_MOVELINEAR:SBR49, L63.7, 1, #tempPosX:LD28, #tempPosY:LD32, #tempPosZ:LD36, #Velocity:LD1, 0, #Acceleration:LD5, #Acceleration:LD5, 200, 1, moveCmdDone:V1041.0, moveCmdBusy:V1041.1, moveCmdActive:V1041.2, moveCmdErr:VB1042
Network 6
// 已运动到取料前位置
LDB=   statState:VB1050, PREPICK
LPS
A      moveCmdDone:V1041.0
MOVB   PICK, statState:VB1050
AENO
R      moveCmdDone:V1041.0, 16
LPP
AB<>   moveCmdErr:VB1042, 0
MOVB   NO_PROCESSING, statState:VB1050
AENO
MOVW   ERR_PROCESSING_INTERN, statStatus:VW1052
AENO
R      statDone:V1040.0, 2
S      statError:V1040.2, 1
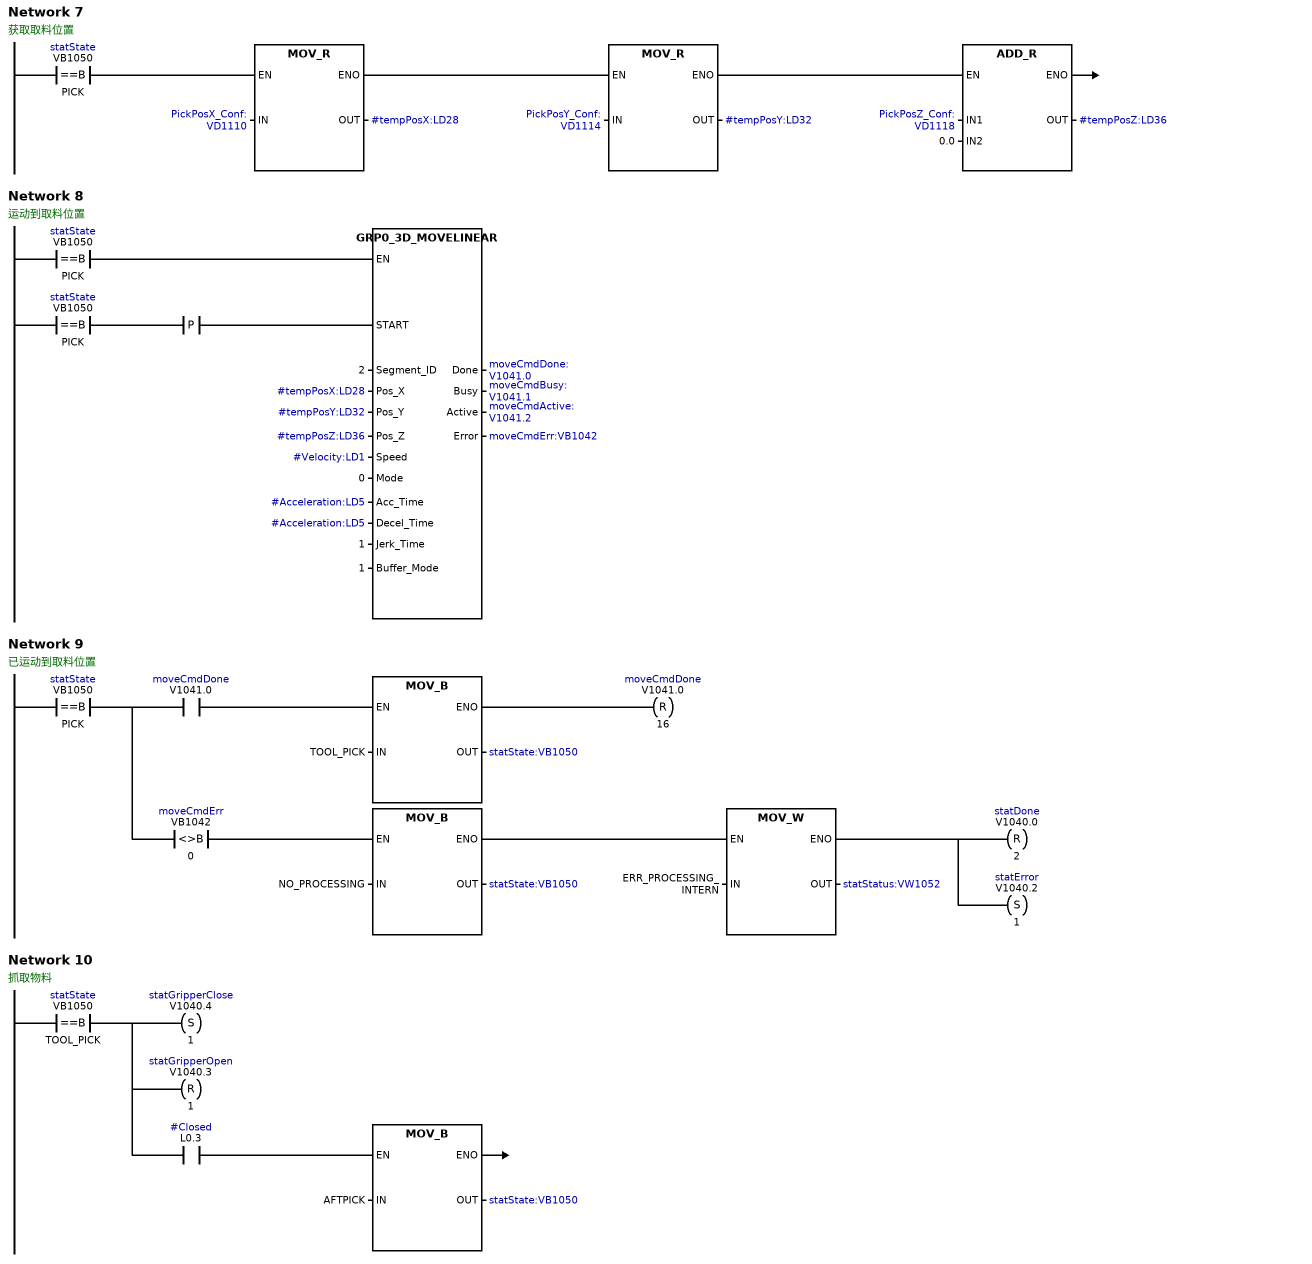
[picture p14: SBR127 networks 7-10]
Network 7
// 获取取料位置
LDB=   statState:VB1050, PICK
MOVR   PickPosX_Conf:VD1110, #tempPosX:LD28
AENO
MOVR   PickPosY_Conf:VD1114, #tempPosY:LD32
AENO
MOVR   PickPosZ_Conf:VD1118, #tempPosZ:LD36
+R     0.0, #tempPosZ:LD36
Network 8
// 运动到取料位置
LDB=   statState:VB1050, PICK
=      L60.0
LDB=   statState:VB1050, PICK
EU
=      L63.7
LD     L60.0
CALL   GRP0_3D_MOVELINEAR:SBR49, L63.7, 2, #tempPosX:LD28, #tempPosY:LD32, #tempPosZ:LD36, #Velocity:LD1, 0, #Acceleration:LD5, #Acceleration:LD5, 1, 1, moveCmdDone:V1041.0, moveCmdBusy:V1041.1, moveCmdActive:V1041.2, moveCmdErr:VB1042
Network 9
// 已运动到取料位置
LDB=   statState:VB1050, PICK
LPS
A      moveCmdDone:V1041.0
MOVB   TOOL_PICK, statState:VB1050
AENO
R      moveCmdDone:V1041.0, 16
LPP
AB<>   moveCmdErr:VB1042, 0
MOVB   NO_PROCESSING, statState:VB1050
AENO
MOVW   ERR_PROCESSING_INTERN, statStatus:VW1052
AENO
R      statDone:V1040.0, 2
S      statError:V1040.2, 1
Network 10
// 抓取物料
LDB=   statState:VB1050, TOOL_PICK
S      statGripperClose:V1040.4, 1
R      statGripperOpen:V1040.3, 1
A      #Closed:L0.3
MOVB   AFTPICK, statState:VB1050
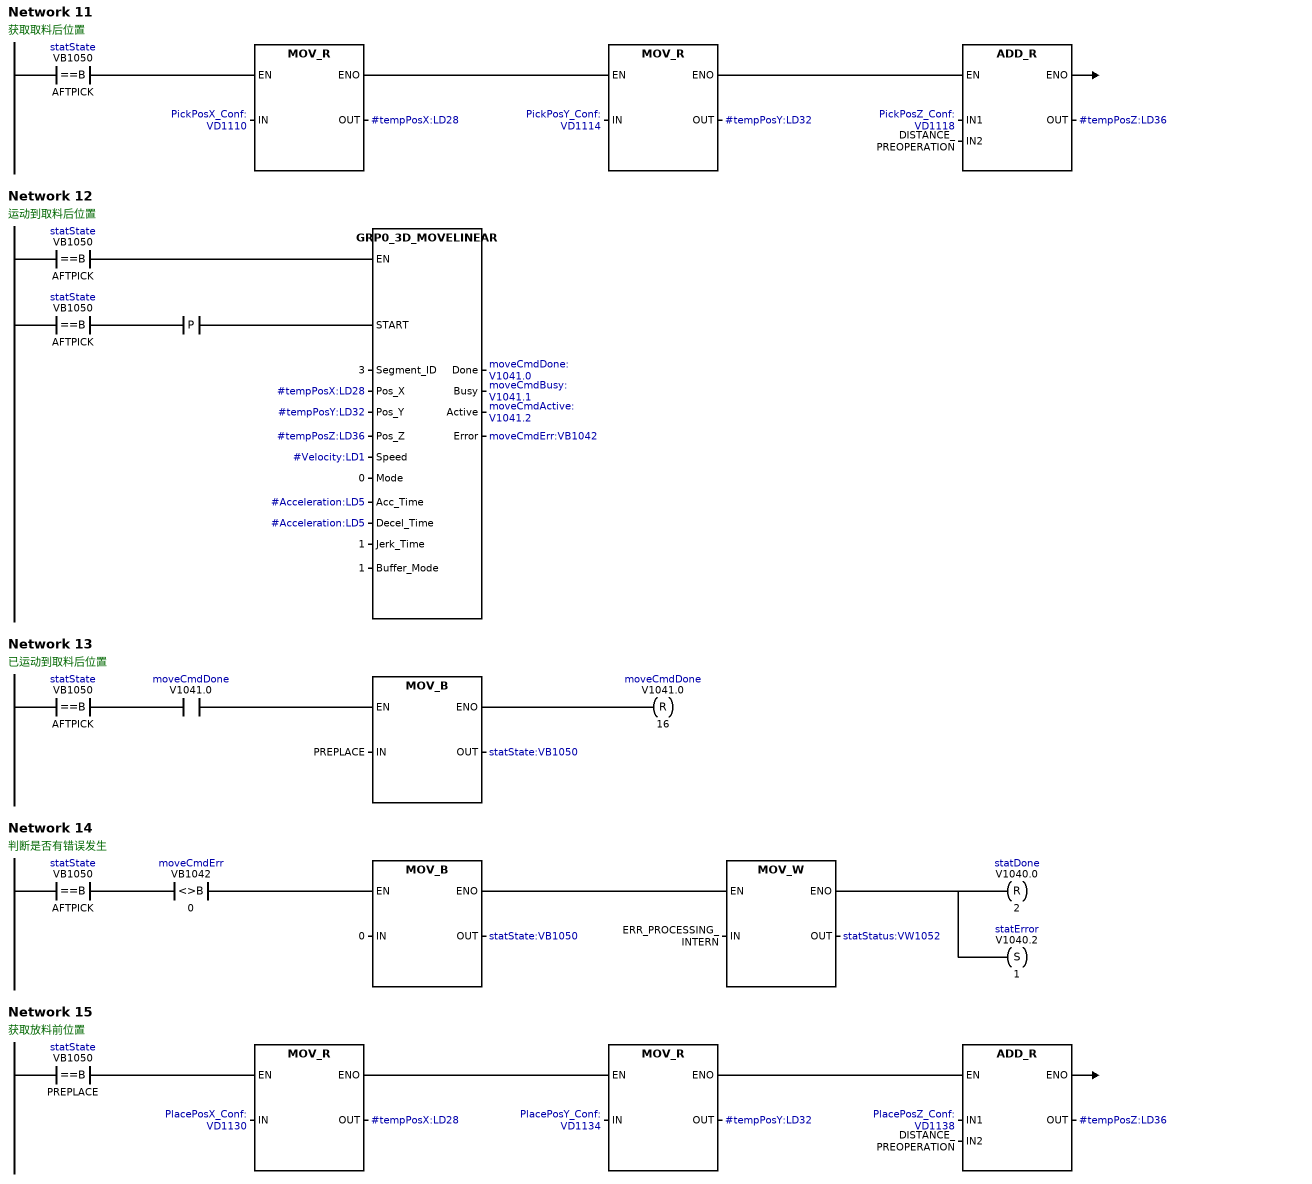
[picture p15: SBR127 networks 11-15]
Network 11
// 获取取料后位置
LDB=   statState:VB1050, AFTPICK
MOVR   PickPosX_Conf:VD1110, #tempPosX:LD28
AENO
MOVR   PickPosY_Conf:VD1114, #tempPosY:LD32
AENO
MOVR   PickPosZ_Conf:VD1118, #tempPosZ:LD36
+R     DISTANCE_PREOPERATION, #tempPosZ:LD36
Network 12
// 运动到取料后位置
LDB=   statState:VB1050, AFTPICK
=      L60.0
LDB=   statState:VB1050, AFTPICK
EU
=      L63.7
LD     L60.0
CALL   GRP0_3D_MOVELINEAR:SBR49, L63.7, 3, #tempPosX:LD28, #tempPosY:LD32, #tempPosZ:LD36, #Velocity:LD1, 0, #Acceleration:LD5, #Acceleration:LD5, 1, 1, moveCmdDone:V1041.0, moveCmdBusy:V1041.1, moveCmdActive:V1041.2, moveCmdErr:VB1042
Network 13
// 已运动到取料后位置
LDB=   statState:VB1050, AFTPICK
A      moveCmdDone:V1041.0
MOVB   PREPLACE, statState:VB1050
AENO
R      moveCmdDone:V1041.0, 16
Network 14
// 判断是否有错误发生
LDB=   statState:VB1050, AFTPICK
AB<>   moveCmdErr:VB1042, 0
MOVB   0, statState:VB1050
AENO
MOVW   ERR_PROCESSING_INTERN, statStatus:VW1052
AENO
R      statDone:V1040.0, 2
S      statError:V1040.2, 1
Network 15
// 获取放料前位置
LDB=   statState:VB1050, PREPLACE
MOVR   PlacePosX_Conf:VD1130, #tempPosX:LD28
AENO
MOVR   PlacePosY_Conf:VD1134, #tempPosY:LD32
AENO
MOVR   PlacePosZ_Conf:VD1138, #tempPosZ:LD36
+R     DISTANCE_PREOPERATION, #tempPosZ:LD36
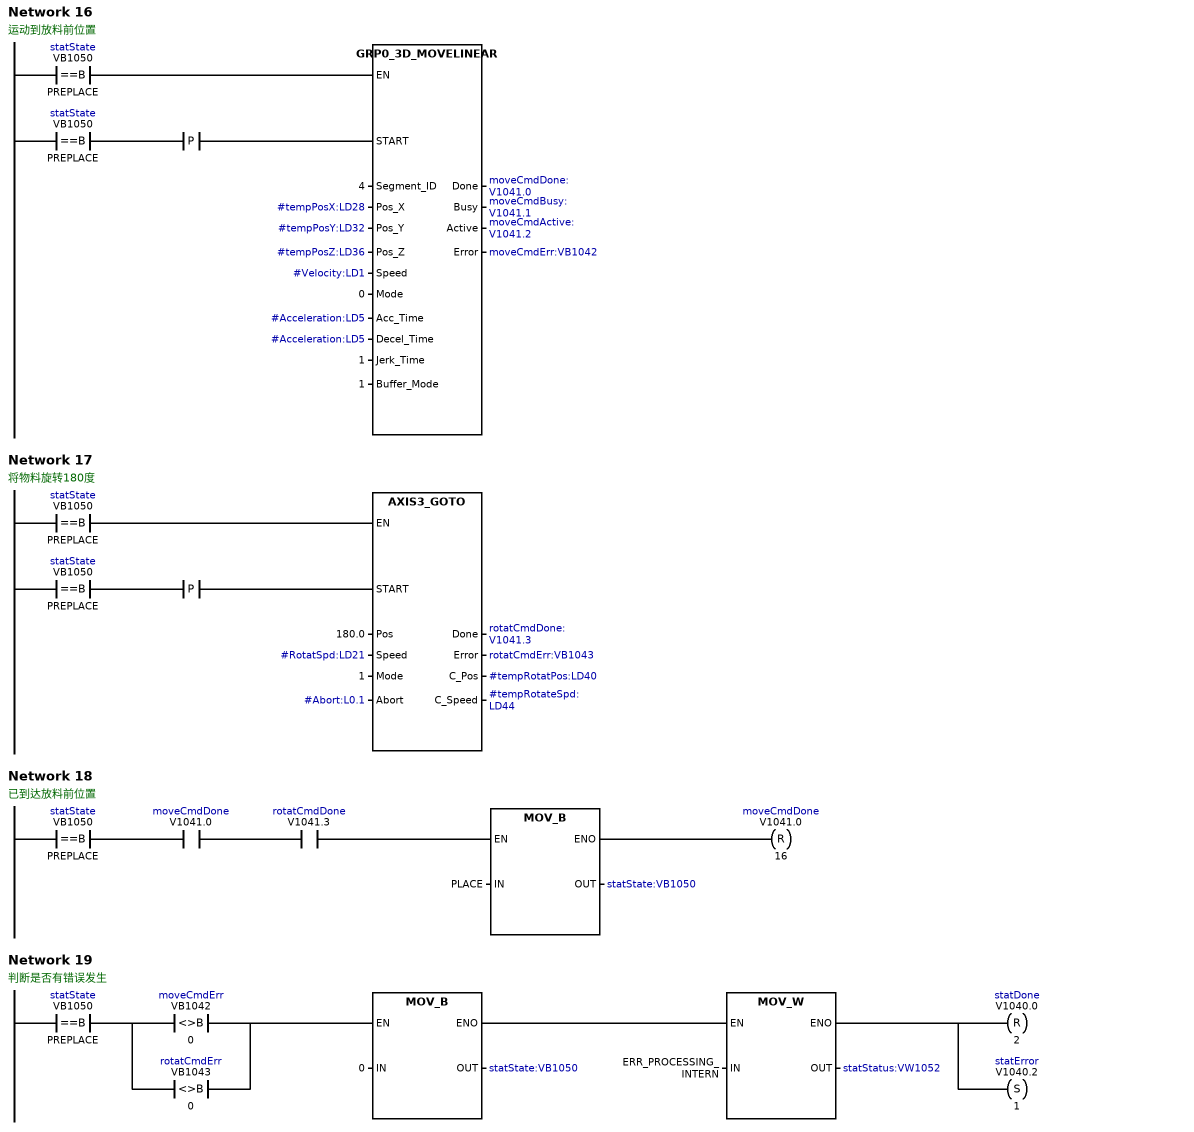
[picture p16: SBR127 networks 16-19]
Network 16
// 运动到放料前位置
LDB=   statState:VB1050, PREPLACE
=      L60.0
LDB=   statState:VB1050, PREPLACE
EU
=      L63.7
LD     L60.0
CALL   GRP0_3D_MOVELINEAR:SBR49, L63.7, 4, #tempPosX:LD28, #tempPosY:LD32, #tempPosZ:LD36, #Velocity:LD1, 0, #Acceleration:LD5, #Acceleration:LD5, 1, 1, moveCmdDone:V1041.0, moveCmdBusy:V1041.1, moveCmdActive:V1041.2, moveCmdErr:VB1042
Network 17
// 将物料旋转180度
LDB=   statState:VB1050, PREPLACE
=      L60.0
LDB=   statState:VB1050, PREPLACE
EU
=      L63.7
LD     L60.0
CALL   AXIS3_GOTO:SBR40, L63.7, 180.0, #RotatSpd:LD21, 1, #Abort:L0.1, rotatCmdDone:V1041.3, rotatCmdErr:VB1043, #tempRotatPos:LD40, #tempRotateSpd:LD44
Network 18
// 已到达放料前位置
LDB=   statState:VB1050, PREPLACE
A      moveCmdDone:V1041.0
A      rotatCmdDone:V1041.3
MOVB   PLACE, statState:VB1050
AENO
R      moveCmdDone:V1041.0, 16
Network 19
// 判断是否有错误发生
LDB=   statState:VB1050, PREPLACE
LDB<>  moveCmdErr:VB1042, 0
OB<>   rotatCmdErr:VB1043, 0
ALD
MOVB   0, statState:VB1050
AENO
MOVW   ERR_PROCESSING_INTERN, statStatus:VW1052
AENO
R      statDone:V1040.0, 2
S      statError:V1040.2, 1
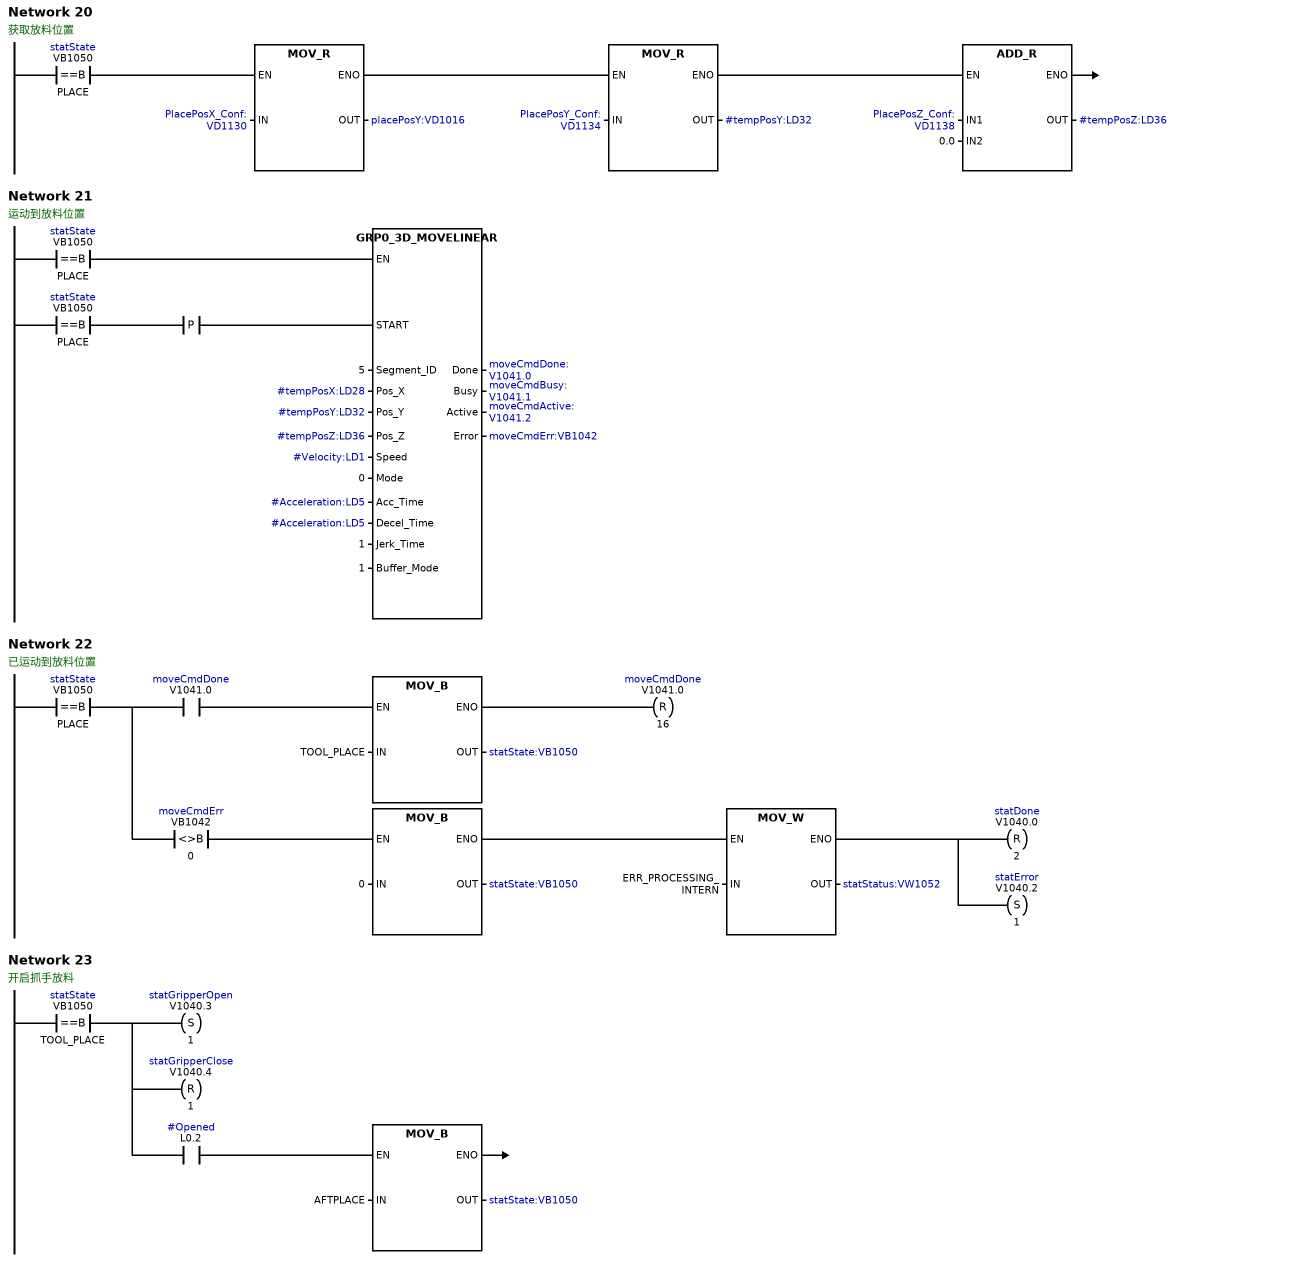
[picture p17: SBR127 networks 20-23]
Network 20
// 获取放料位置
LDB=   statState:VB1050, PLACE
MOVR   PlacePosX_Conf:VD1130, placePosY:VD1016
AENO
MOVR   PlacePosY_Conf:VD1134, #tempPosY:LD32
AENO
MOVR   PlacePosZ_Conf:VD1138, #tempPosZ:LD36
+R     0.0, #tempPosZ:LD36
Network 21
// 运动到放料位置
LDB=   statState:VB1050, PLACE
=      L60.0
LDB=   statState:VB1050, PLACE
EU
=      L63.7
LD     L60.0
CALL   GRP0_3D_MOVELINEAR:SBR49, L63.7, 5, #tempPosX:LD28, #tempPosY:LD32, #tempPosZ:LD36, #Velocity:LD1, 0, #Acceleration:LD5, #Acceleration:LD5, 1, 1, moveCmdDone:V1041.0, moveCmdBusy:V1041.1, moveCmdActive:V1041.2, moveCmdErr:VB1042
Network 22
// 已运动到放料位置
LDB=   statState:VB1050, PLACE
LPS
A      moveCmdDone:V1041.0
MOVB   TOOL_PLACE, statState:VB1050
AENO
R      moveCmdDone:V1041.0, 16
LPP
AB<>   moveCmdErr:VB1042, 0
MOVB   0, statState:VB1050
AENO
MOVW   ERR_PROCESSING_INTERN, statStatus:VW1052
AENO
R      statDone:V1040.0, 2
S      statError:V1040.2, 1
Network 23
// 开启抓手放料
LDB=   statState:VB1050, TOOL_PLACE
S      statGripperOpen:V1040.3, 1
R      statGripperClose:V1040.4, 1
A      #Opened:L0.2
MOVB   AFTPLACE, statState:VB1050
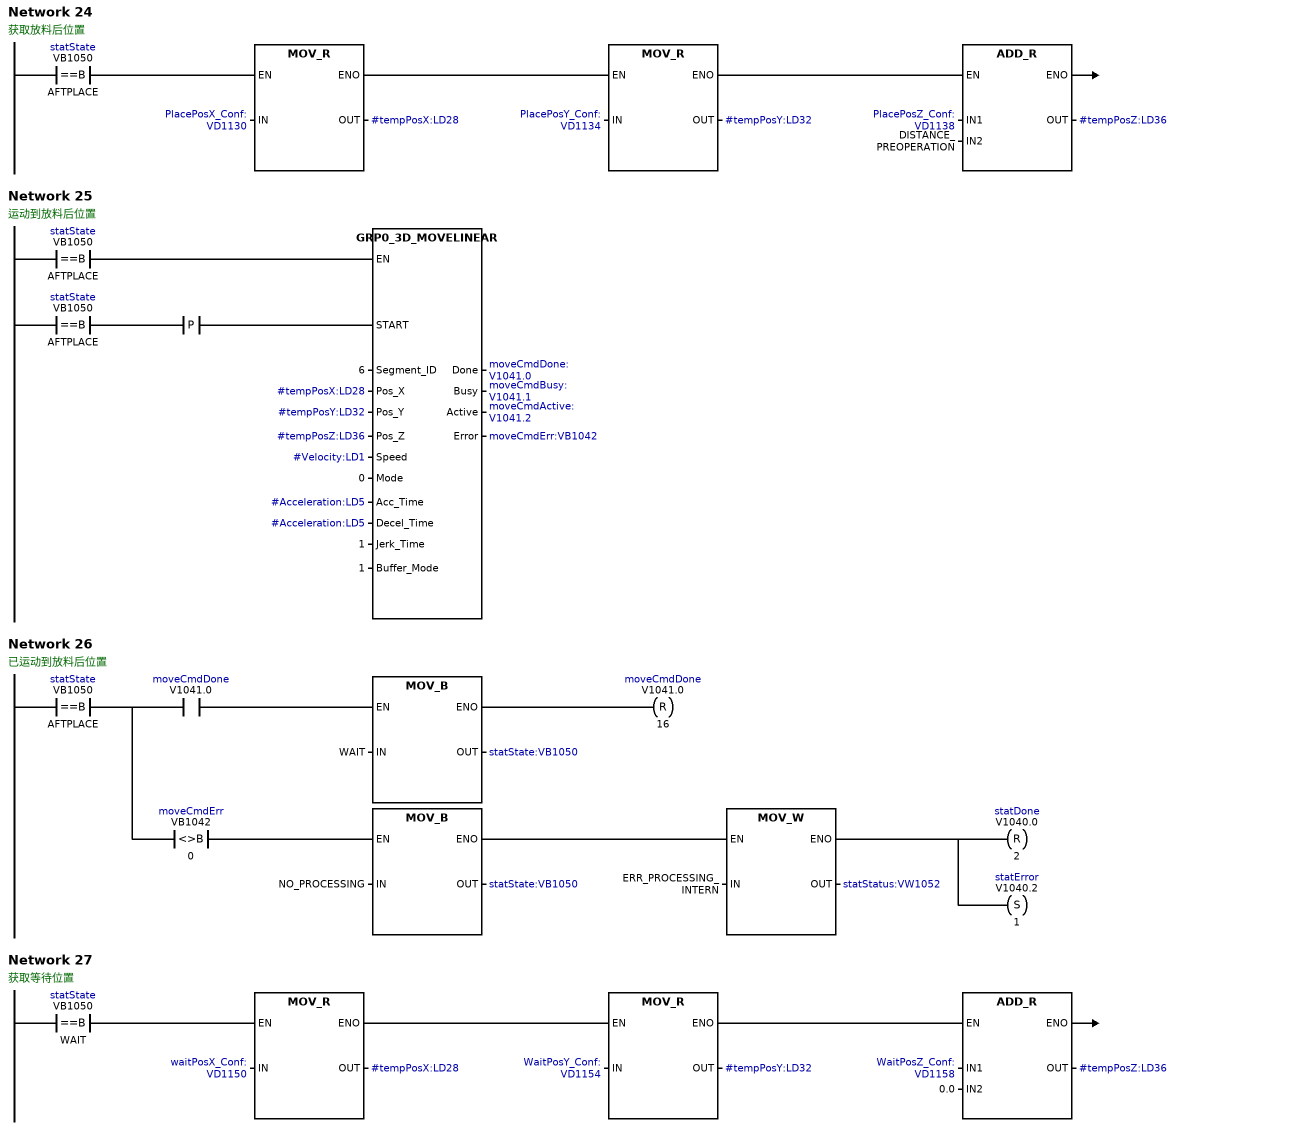
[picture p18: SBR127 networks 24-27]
Network 24
// 获取放料后位置
LDB=   statState:VB1050, AFTPLACE
MOVR   PlacePosX_Conf:VD1130, #tempPosX:LD28
AENO
MOVR   PlacePosY_Conf:VD1134, #tempPosY:LD32
AENO
MOVR   PlacePosZ_Conf:VD1138, #tempPosZ:LD36
+R     DISTANCE_PREOPERATION, #tempPosZ:LD36
Network 25
// 运动到放料后位置
LDB=   statState:VB1050, AFTPLACE
=      L60.0
LDB=   statState:VB1050, AFTPLACE
EU
=      L63.7
LD     L60.0
CALL   GRP0_3D_MOVELINEAR:SBR49, L63.7, 6, #tempPosX:LD28, #tempPosY:LD32, #tempPosZ:LD36, #Velocity:LD1, 0, #Acceleration:LD5, #Acceleration:LD5, 1, 1, moveCmdDone:V1041.0, moveCmdBusy:V1041.1, moveCmdActive:V1041.2, moveCmdErr:VB1042
Network 26
// 已运动到放料后位置
LDB=   statState:VB1050, AFTPLACE
LPS
A      moveCmdDone:V1041.0
MOVB   WAIT, statState:VB1050
AENO
R      moveCmdDone:V1041.0, 16
LPP
AB<>   moveCmdErr:VB1042, 0
MOVB   NO_PROCESSING, statState:VB1050
AENO
MOVW   ERR_PROCESSING_INTERN, statStatus:VW1052
AENO
R      statDone:V1040.0, 2
S      statError:V1040.2, 1
Network 27
// 获取等待位置
LDB=   statState:VB1050, WAIT
MOVR   waitPosX_Conf:VD1150, #tempPosX:LD28
AENO
MOVR   WaitPosY_Conf:VD1154, #tempPosY:LD32
AENO
MOVR   WaitPosZ_Conf:VD1158, #tempPosZ:LD36
+R     0.0, #tempPosZ:LD36
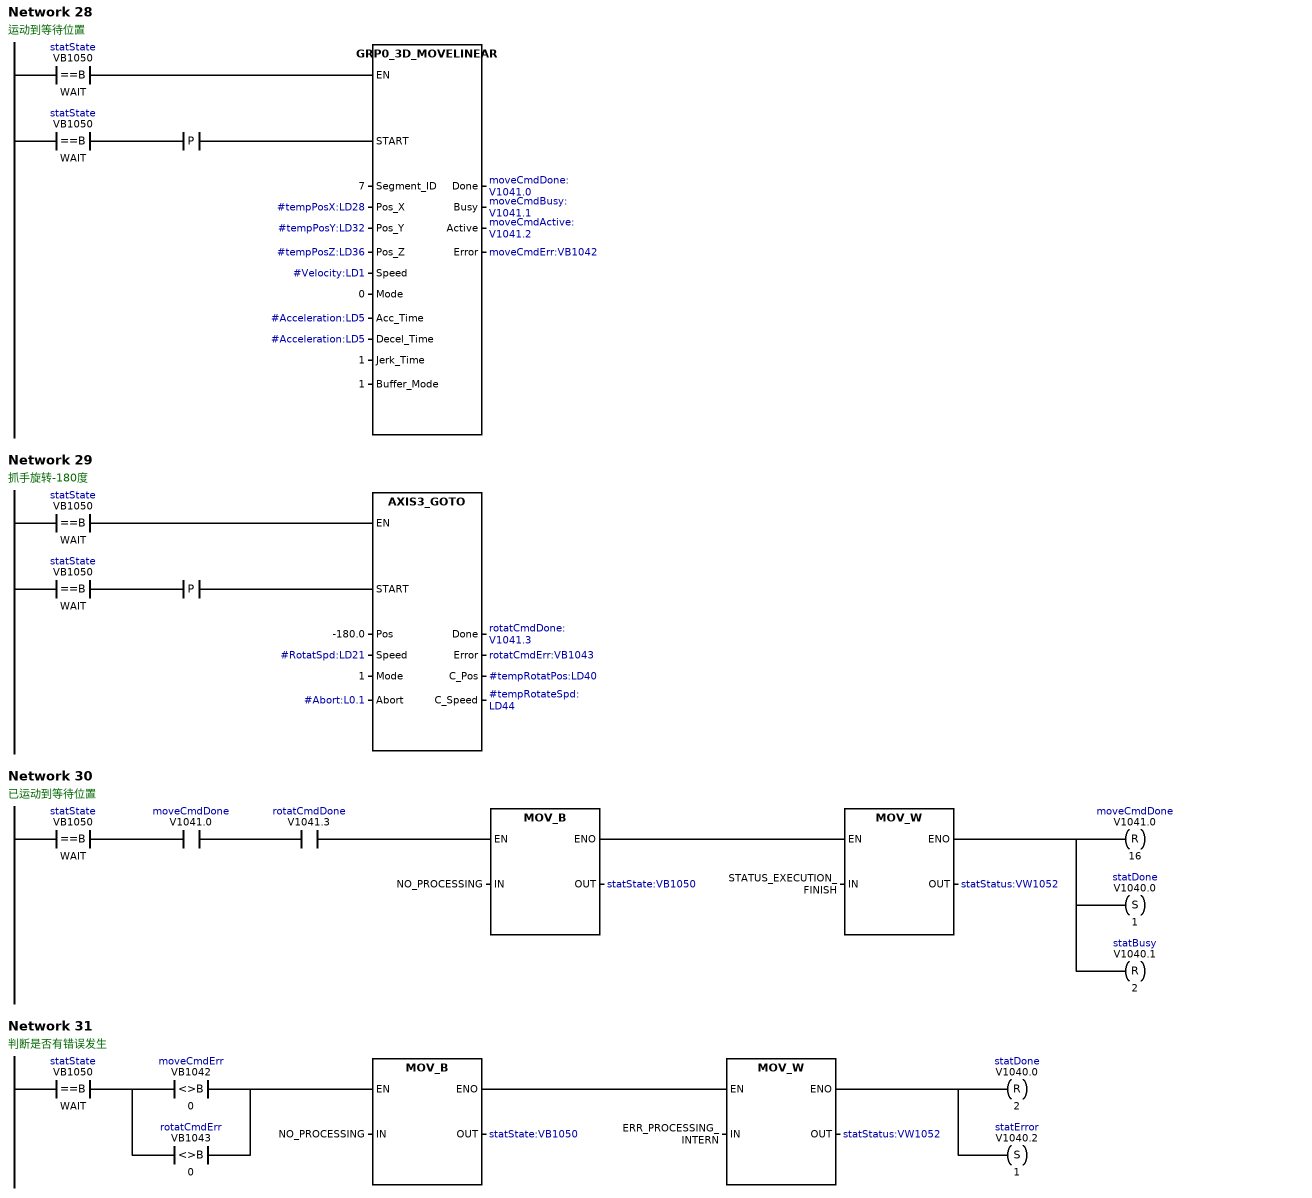
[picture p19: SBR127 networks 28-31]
Network 28
// 运动到等待位置
LDB=   statState:VB1050, WAIT
=      L60.0
LDB=   statState:VB1050, WAIT
EU
=      L63.7
LD     L60.0
CALL   GRP0_3D_MOVELINEAR:SBR49, L63.7, 7, #tempPosX:LD28, #tempPosY:LD32, #tempPosZ:LD36, #Velocity:LD1, 0, #Acceleration:LD5, #Acceleration:LD5, 1, 1, moveCmdDone:V1041.0, moveCmdBusy:V1041.1, moveCmdActive:V1041.2, moveCmdErr:VB1042
Network 29
// 抓手旋转-180度
LDB=   statState:VB1050, WAIT
=      L60.0
LDB=   statState:VB1050, WAIT
EU
=      L63.7
LD     L60.0
CALL   AXIS3_GOTO:SBR40, L63.7, -180.0, #RotatSpd:LD21, 1, #Abort:L0.1, rotatCmdDone:V1041.3, rotatCmdErr:VB1043, #tempRotatPos:LD40, #tempRotateSpd:LD44
Network 30
// 已运动到等待位置
LDB=   statState:VB1050, WAIT
A      moveCmdDone:V1041.0
A      rotatCmdDone:V1041.3
MOVB   NO_PROCESSING, statState:VB1050
AENO
MOVW   STATUS_EXECUTION_FINISH, statStatus:VW1052
AENO
R      moveCmdDone:V1041.0, 16
S      statDone:V1040.0, 1
R      statBusy:V1040.1, 2
Network 31
// 判断是否有错误发生
LDB=   statState:VB1050, WAIT
LDB<>  moveCmdErr:VB1042, 0
OB<>   rotatCmdErr:VB1043, 0
ALD
MOVB   NO_PROCESSING, statState:VB1050
AENO
MOVW   ERR_PROCESSING_INTERN, statStatus:VW1052
AENO
R      statDone:V1040.0, 2
S      statError:V1040.2, 1
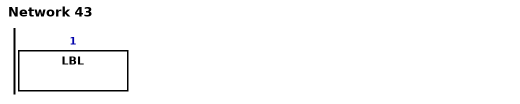
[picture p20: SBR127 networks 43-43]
Network 43
LBL    1
END_SUBROUTINE_BLOCK

DATA_BLOCK_TAB PnP
BEGIN
//数据页注释
//按 F1 获取帮助和示例数据页
         PickPosX_Conf, 150.0
         PickPosY_Conf, 0.0
         PickPosZ_Conf, 0.0
         PlacePosX_Conf, 0.0
         PlacePosY_Conf, 61.0885
         PlacePosZ_Conf, 0.0
         waitPosX_Conf, 0.0
         WaitPosY_Conf, 61.0885
         WaitPosZ_Conf, 10.0
         Spd3D, 200.0
         SpdRotat, 20.0
END_DATA_BLOCK_TAB

DATA_BLOCK_TAB MovePath
BEGIN
//数据页注释
//按 F1 获取帮助和示例数据页
         statStatus, 16#7000
END_DATA_BLOCK_TAB
